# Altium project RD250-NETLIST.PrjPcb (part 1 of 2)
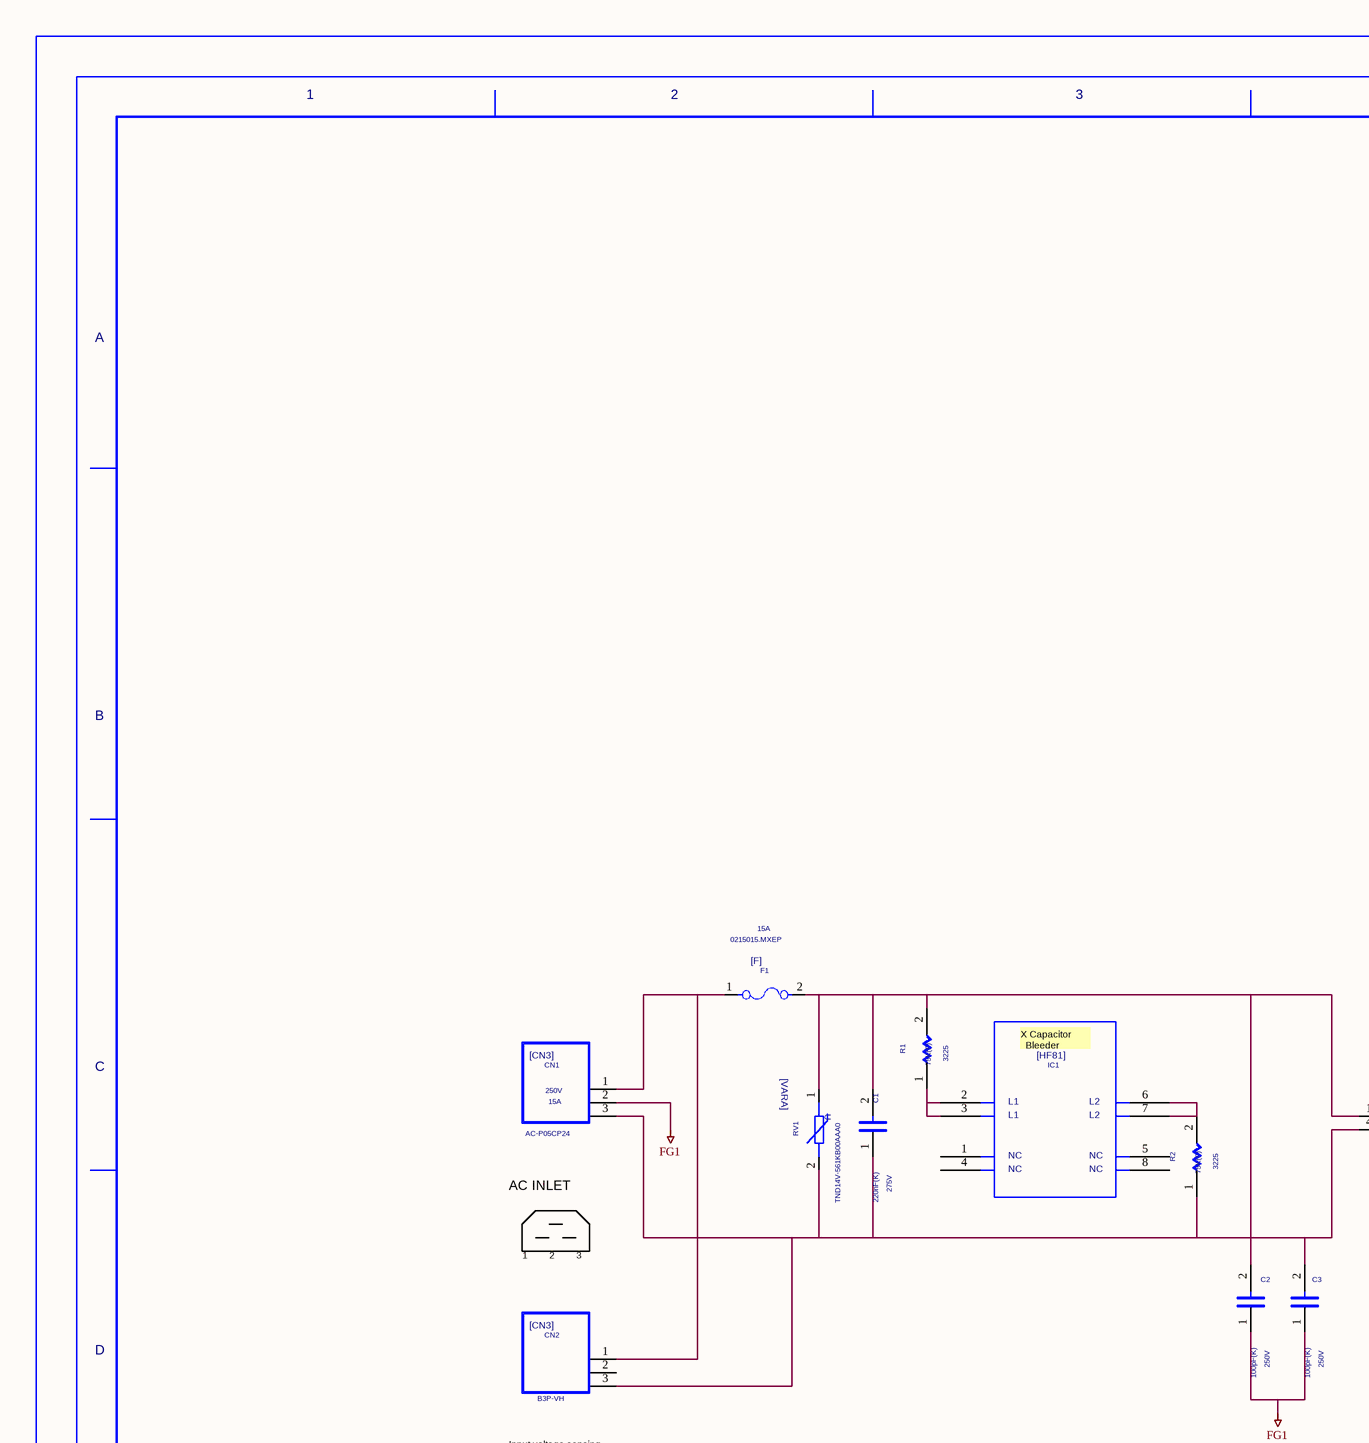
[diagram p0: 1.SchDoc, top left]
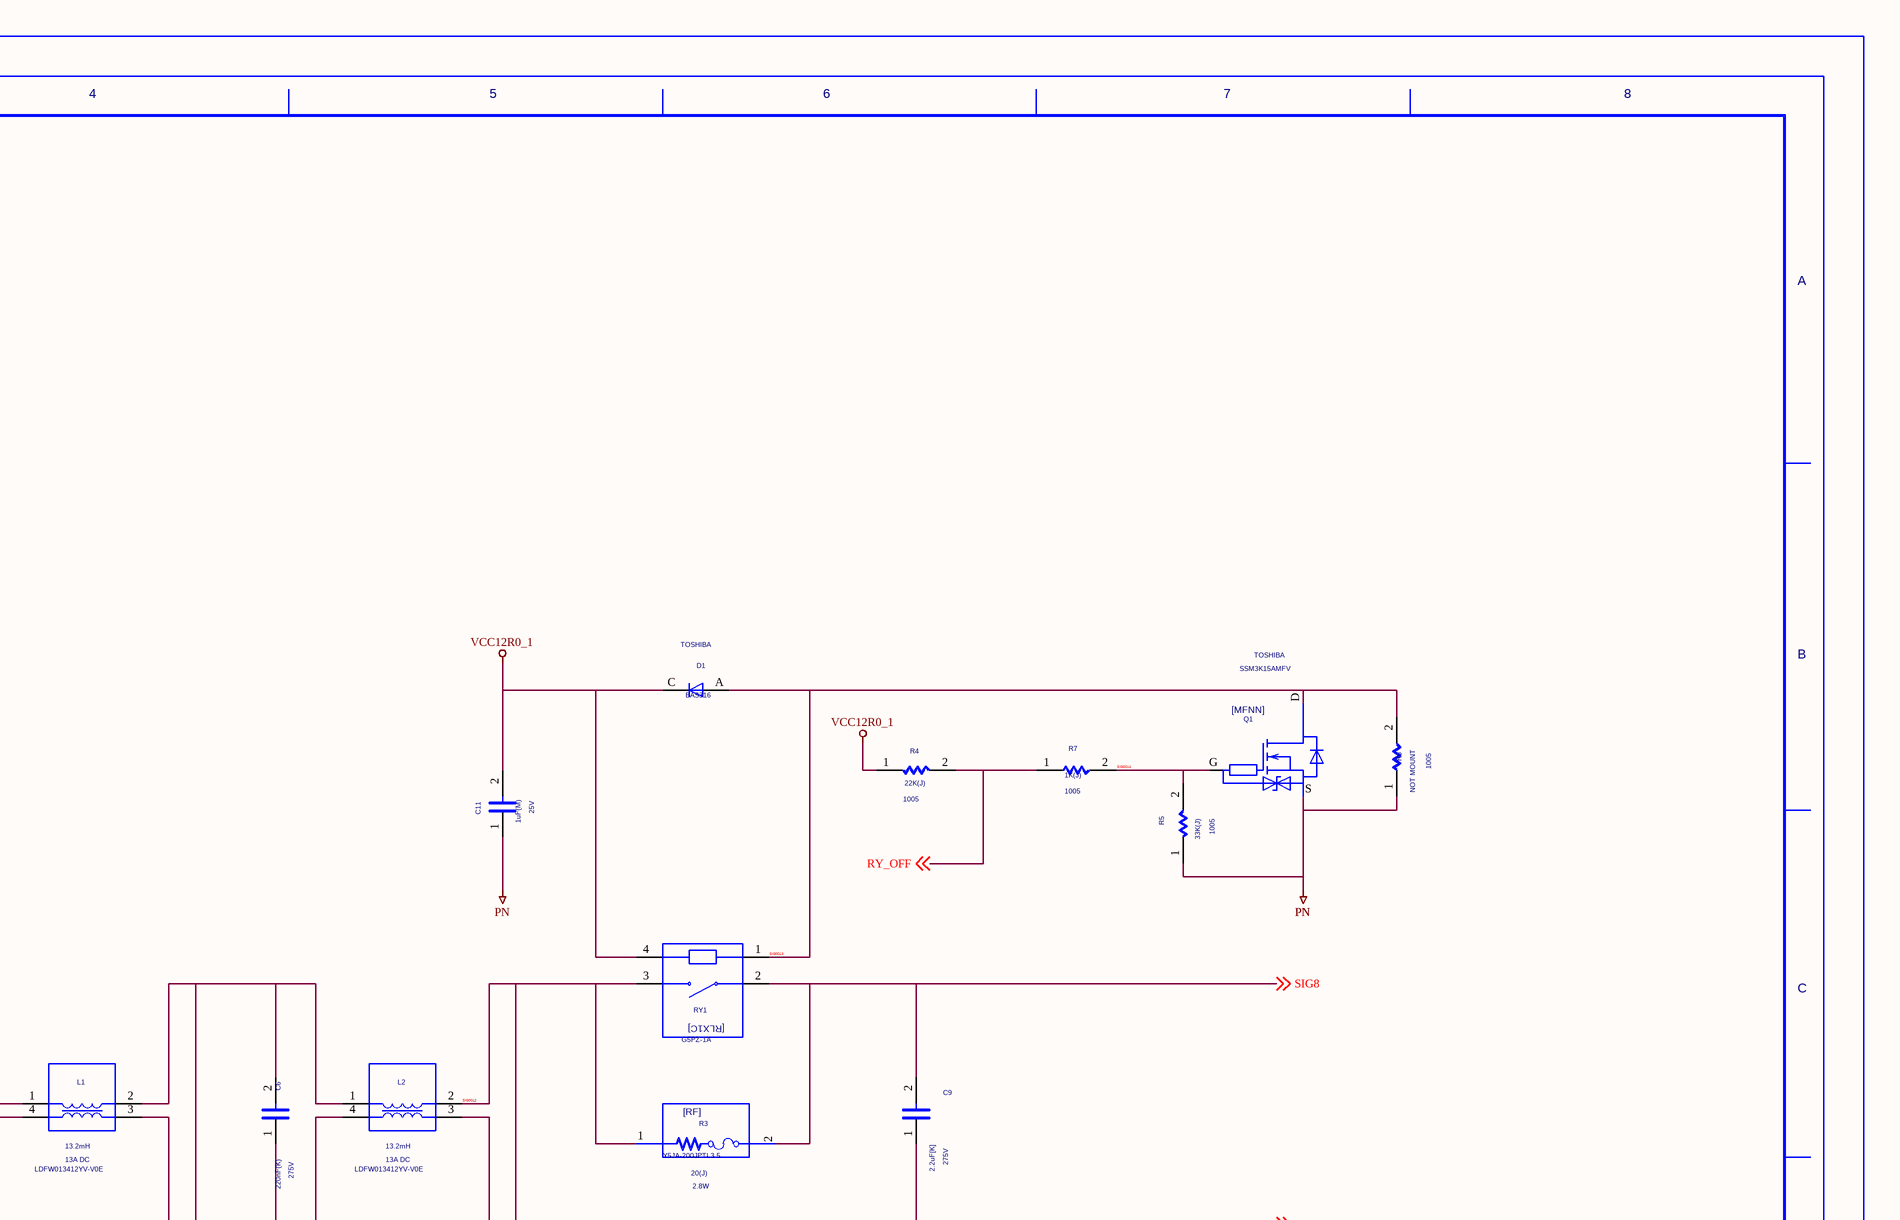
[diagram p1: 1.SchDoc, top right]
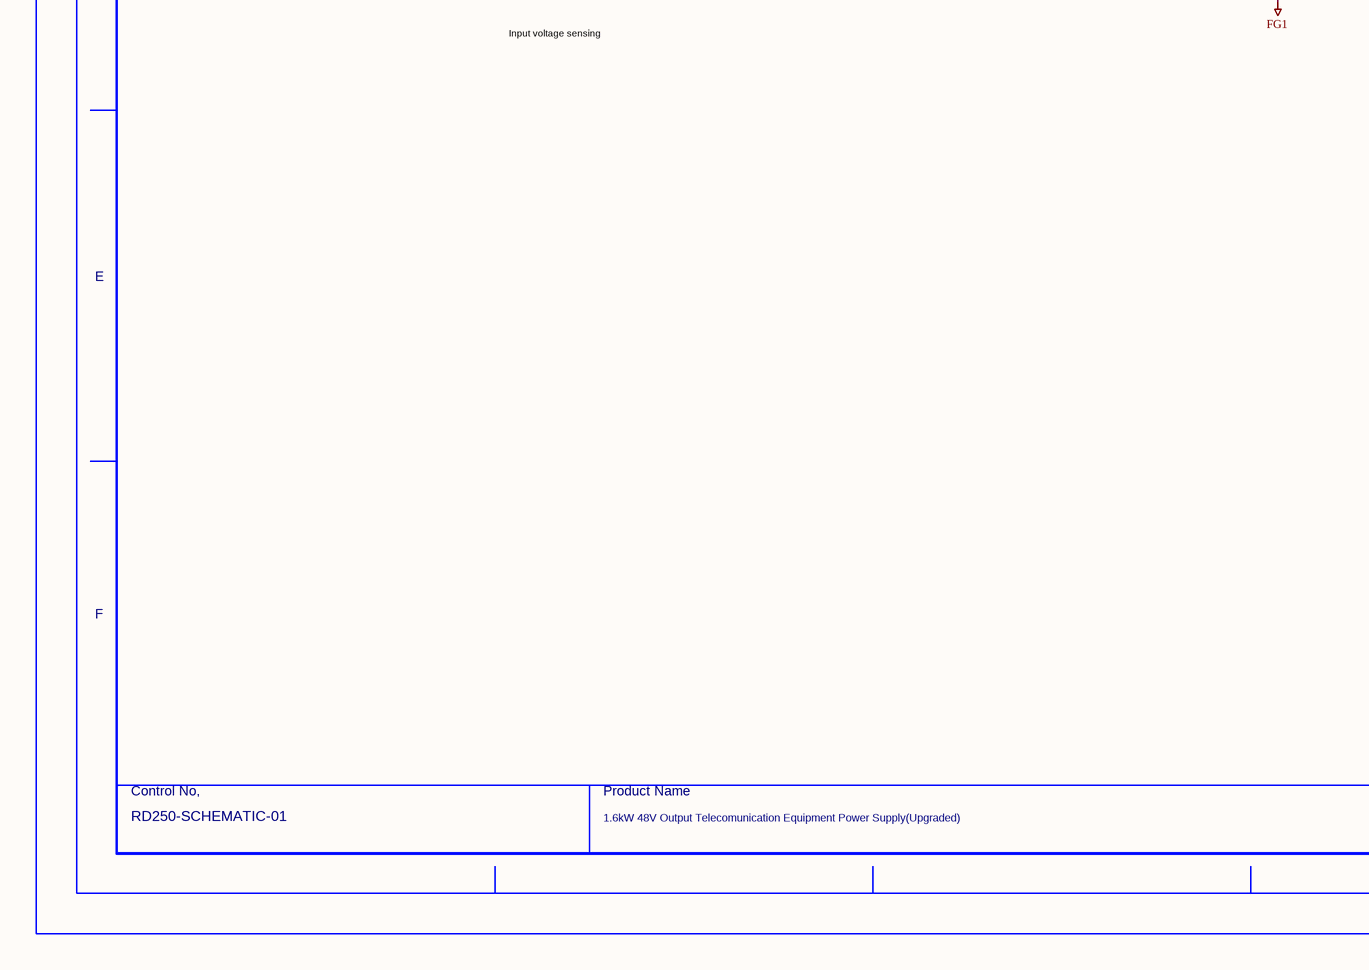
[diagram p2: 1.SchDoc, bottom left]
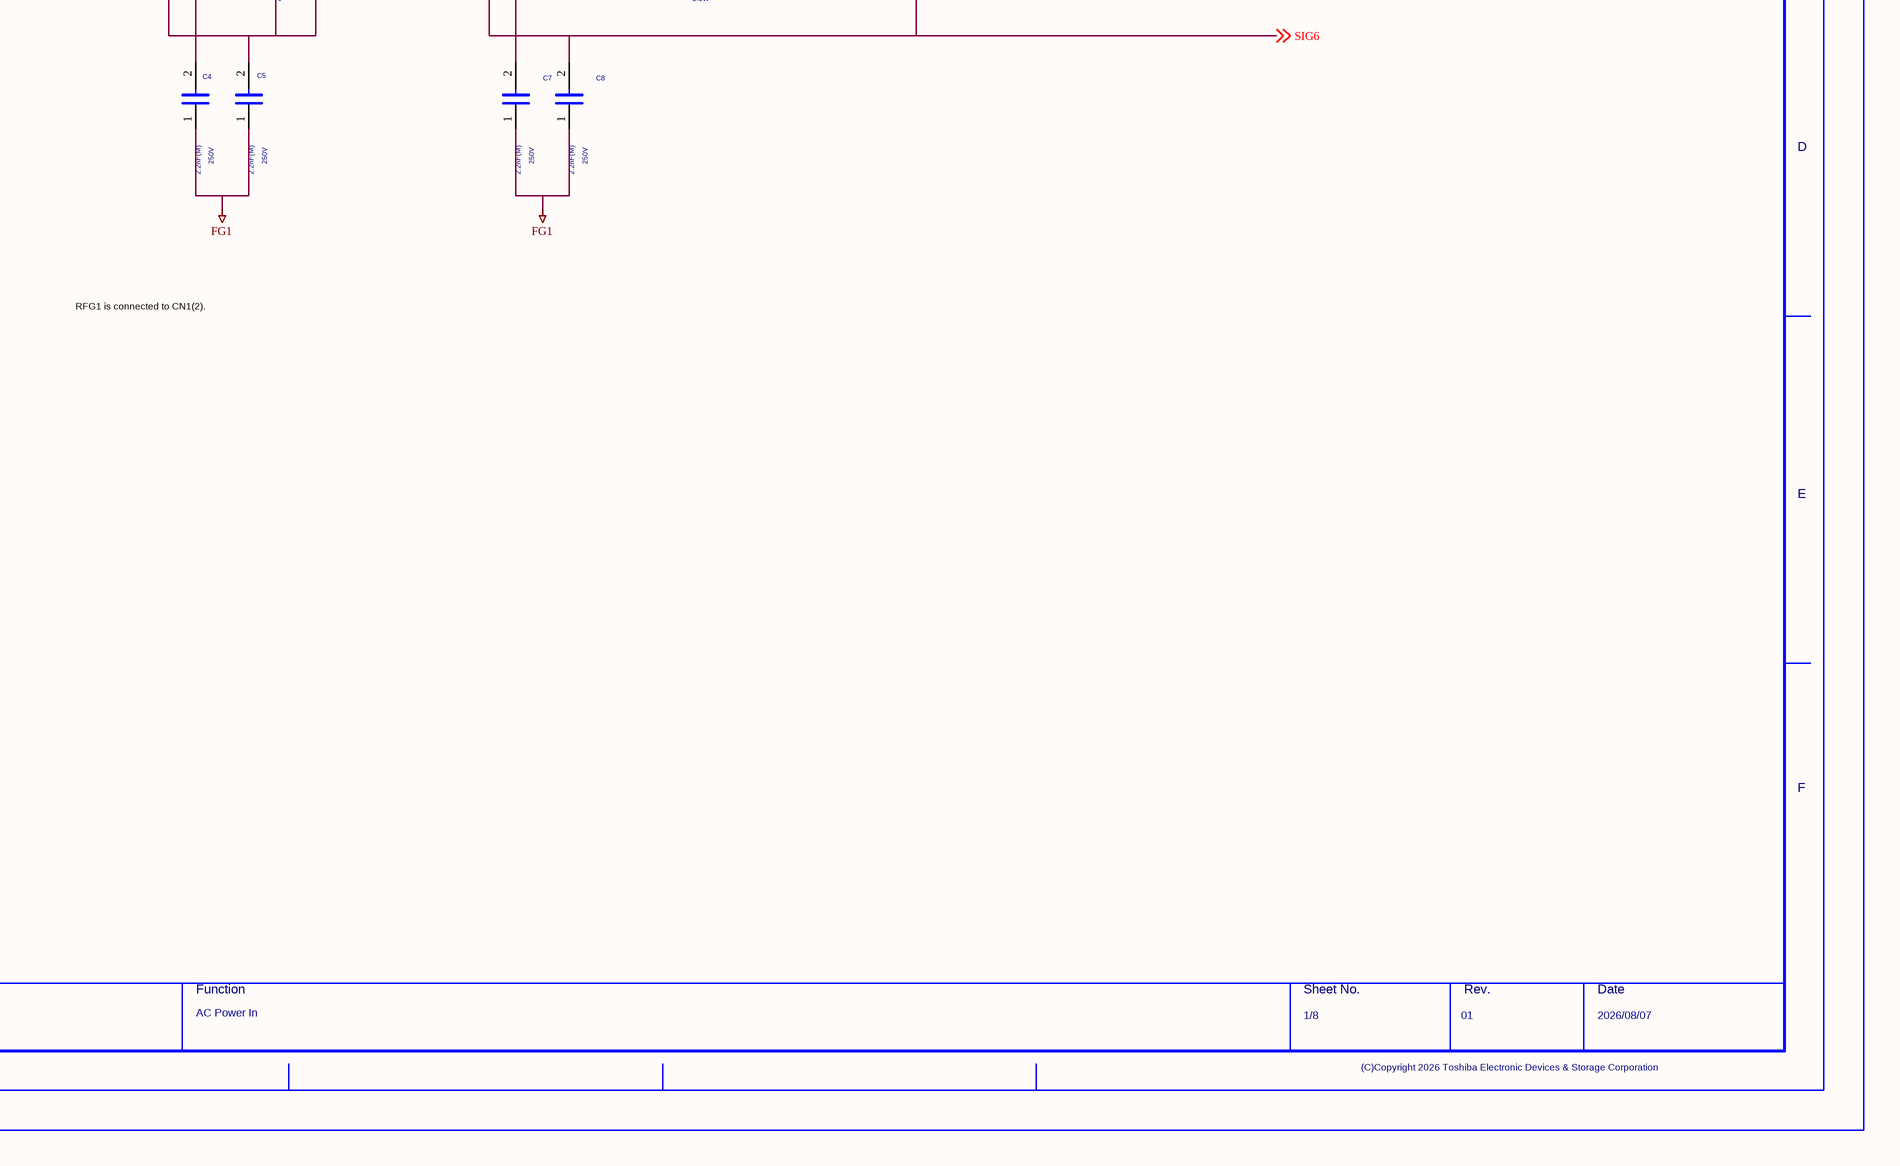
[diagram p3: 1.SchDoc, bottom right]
8 sheets, 547 parts. Net scope: global (net labels, ports and power ports of the same name join across sheets).
Sheets:
  1.SchDoc
  2.SchDoc
  3.SchDoc
  4.SchDoc
  5.SchDoc
  6.SchDoc
  7.SchDoc
  8.SchDoc

## Sheet 1.SchDoc
size 599 x 434 mm

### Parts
(Parts that share a designator on the sheet are numbered #1, #2 ... from top to bottom, then left to right.)
C1  VAL1: 220nF(K)  VAL2: 275V  (hidden comment: C)
C2  VAL1: 100pF(K)  VAL2: 250V  (hidden comment: DE2B3SA101KA3BT02F)
C3  VAL1: 100pF(K)  VAL2: 250V  (hidden comment: DE2B3SA101KA3BT02F)
C4  VAL1: 2.2nF(M)  VAL2: 250V  (hidden comment: DE2E3SA222MN3AT02F)
C5  VAL1: 2.2nF(M)  VAL2: 250V  (hidden comment: DE2E3SA222MN3AT02F)
C6  VAL1: 220nF(K)  VAL2: 275V  (hidden comment: C)
C7  VAL1: 2.2nF(M)  VAL2: 250V  (hidden comment: DE2E3SA222MN3AT02F)
C8  VAL1: 2.2nF(M)  VAL2: 250V  (hidden comment: DE2E3SA222MN3AT02F)
C9  VAL1: 2.2uF[K]  VAL2: 275V  (hidden comment: C)
C11  VAL1: 1uF(M)  VAL2: 25V  (hidden comment: C)
CN1  VAL2: 250V  VAL1: 15A  VAL3: AC-P05CP24  (hidden comment: CN3)
CN2  VAL3: B3P-VH  (hidden comment: CN3)
D1  USERCOMPTEXT3: TOSHIBA  VAL3: BAS316  (hidden comment: D)
F1  VAL1: 15A  VAL3: 0215015.MXEP  (hidden comment: F)
IC1  L81  (value not drawn)
L1  VAL1: 13.2mH  VAL2: 13A DC  (hidden comment: LDFW013412YV-V0E)
L2  VAL1: 13.2mH  VAL2: 13A DC  (hidden comment: LDFW013412YV-V0E)
Q1  USERCOMPTEXT3: TOSHIBA  VAL3: SSM3K15AMFV  (hidden comment: MFNN)
R1  VAL1: 75K(F)  SIZECODESMD: 3225  (hidden comment: R)
R2  VAL1: 75K(F)  SIZECODESMD: 3225  (hidden comment: R)
R3  VAL3: Y5JA-200JPTL3.5  VAL1: 20(J)  VAL2: 2.8W  (hidden comment: Y5JA-330JPTL3_5)
R4  VAL1: 22K(J)  SIZECODESMD: 1005  (hidden comment: R)
R5  VAL1: 33K(J)  SIZECODESMD: 1005  (hidden comment: R)
R6  NOTMOUNT: NOT MOUNT  SIZECODESMD: 1005  (hidden comment: R)
R7  VAL1: 1K(J)  SIZECODESMD: 1005  (hidden comment: R)
RV1  VAL3: TND14V-561KB00AAA0  (hidden comment: VARA)
RY1  G5PZ-1A
U?#1  DATE: 2026/08/07  DRAWINGNUMBER: RD250-SCHEMATIC-01  TITLE: 1.6kW 48V Output Telecomunication / Equipment Power Supply(Upgraded)  FUNCTION: AC Power In  SHEETNUMBER: 1/8  REVISION: 01  (hidden comment: WAKU_A3_TDSC_PSDEV_LOCAL)

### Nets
FG1: C2.1 C3.1 C4.1 C5.1 C7.1 C8.1 CN1.2
PN: C11.1 Q1.S R5.1 R6.1
VCC12R0_1: C11.2 D1.C R4.1 RY1.4
RY_OFF: R4.2 R7.1 ; off-sheet RY_OFF
SIG1: C1.2 C2.2 F1.2 L1.1 R1.2 RV1.1
SIG2: C1.1 C3.2 CN1.3 CN2.3 L1.4 R2.1 RV1.2
SIG6: C8.2 C9.1 L2.3 ; off-sheet SIG6
SIG8: C9.2 R3.2 RY1.2 ; off-sheet SIG8
SIG9: IC1.2 IC1.3 R1.1
SIG10: IC1.6 IC1.7 R2.2
SIG0012: C7.2 L2.2 R3.1 RY1.3
SIG0013: D1.A Q1.D R6.2 RY1.1
SIG0014: Q1.G R5.2 R7.2
SIG193: CN1.1 CN2.1 F1.1
SIG199: C4.2 C6.2 L1.2 L2.1
SIG200: C5.2 C6.1 L1.3 L2.4

Not connected (* = marked no-connect by the designer): CN2 2; IC1 1 4 5 8

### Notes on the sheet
- AC INLET
- 1
- 2
- 3
- Input voltage sensing
- RFG1 is connected to CN1(2).

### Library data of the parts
C1 C6 = C_Dup1: OriginalSymbolOrigin: (2540,7620); VAL3: LE224-M; COMP: PRT_17; MAXGCOUNT: 1; SIZECODESMD: DIP; SAVECOUNT: 0
C2 C3 = DE2B3SA101KA3BT02F: TIME: 18:06:52; UPDATEUSER: t6860224; SAVECOUNT: 1; OriginalSymbolOrigin: (2540,7620); SIZECODESMD: DIP; CHIPSIZE: }}¦}¦¦7.5mmﾘ・
C4 C7 C8 = DE2E3SA222MN3AT02F: TIME: 18:04:40; UPDATEUSER: t6860224; UPDATETIME: 18:05:46; SAVECOUNT: 2; OriginalSymbolOrigin: (2540,7620); CHIPSIZE: }}¦}¦¦7.5mmﾘ・; MAXGCOUNT: 1; SIZECODESMD: DIP
C5 = DE2E3SA222MN3AT02F: SQ_PART_MODEL: CON_2.2N; TIME: 18:04:40; UPDATEUSER: t6860224; UPDATETIME: 18:05:46; SAVECOUNT: 2; OriginalSymbolOrigin: (2540,7620); CHIPSIZE: }}¦}¦¦7.5mmﾘ・; MAXGCOUNT: 1; SIZECODESMD: DIP; ADSCNVFLAG: ON
C9 = C_Dup1: OriginalSymbolOrigin: (2540,7620); VAL3: 890324026034CS; COMP: PRT_18; MAXGCOUNT: 1; SIZECODESMD: DIP; SAVECOUNT: 0
C11 = C_Dup1: OriginalSymbolOrigin: (2540,7620); COMP: PRT_52; CHIPSIZE: 1005; MAXGCOUNT: 1; SAVECOUNT: 0
CN1 = CN3_Dup1: OriginalSymbolOrigin: (2540,17780); COMP: PRT_61; SAVECOUNT: 0
CN2 = CN3: OriginalSymbolOrigin: (2540,17780); USERCOMPTEXT3: }}¦}¦¦; MAXGCOUNT: 1; COMP: G36220401068; ADSCNVFLAG: ON; SAVECOUNT: 0
D1 = D_Dup1: SAVEAREA0: -225,-91,12804,7836; SAVECOUNT: 3; TIME: 14:49:55; UPDATEUSER: 19870035; UPDATETIME: 14:20:16; OriginalSymbolOrigin: (5080,5080); USERCOMPTEXT2: 100V,0.25A; COMP: PRT_26; MAXGCOUNT: 1
F1 = F_Dup1: OriginalSymbolOrigin: (2540,5080); COMP: PRT_21; MAXGCOUNT: 1; SAVECOUNT: 0
IC1 = L81: SAVEAREA0: -12429,-3512,55842,41521; TIME: 18:31:00; UPDATEUSER: cae; UPDATETIME: 11:10:50; SAVECOUNT: 13; OriginalSymbolOrigin: (7620,35560); VAL3: HF81; COMP: PRT_45
L1 L2 = LDFW013412YV-V0E: SAVEAREA0: -19486,-4937,42112,22919; TIME: 15:15:31; UPDATEUSER: t4887876; UPDATETIME: 16:45:41; SAVECOUNT: 10; OriginalSymbolOrigin: (5080,15240); USERCOMPTEXT1: #%ﾘ%; DEVICENAME: DLW21HN670SQ2
Q1 = MFNN: SAVECOUNT: 25; SAVEAREA0: -2884,-274,25430,18334; TIME: 08:01:03; UPDATEUSER: sato-yr; UPDATETIME: 13:42:20; OriginalSymbolOrigin: (2540,17780); MAXGCOUNT: 1; COMP: GDM410000663; ADSCNVFLAG: ON; ADSCOMPONENTNAME: Q_MFNN
R1 R2 = R_Dup1: VAL2: 500mW; OriginalSymbolOrigin: (5080,5080); COMP: PRT_23; MAXGCOUNT: 1; SAVECOUNT: 0
R3 = Y5JA-330JPTL3_5: TIME: 16:26:39; UPDATEUSER: t4887876; UPDATETIME: 20:40:35; SAVECOUNT: 5; OriginalSymbolOrigin: (-1270,12700); MAXGCOUNT: 1; CHIPSIZE: 13x9xH25.5
R4 R5 R7 = R_Dup1: VAL2: 63mW; OriginalSymbolOrigin: (5080,5080); COMP: GDM010004481; CHIPSIZE: 1608; MAXGCOUNT: 1; SAVECOUNT: 0
R6 = R_Dup1: OriginalSymbolOrigin: (5080,5080); COMP: GDM010004481; CHIPSIZE: 1608; MAXGCOUNT: 1; SAVECOUNT: 0
RV1 = VARA: SAVEAREA0: -9950,-8554,25168,13619; SAVECOUNT: 12; TIME: 09:56:50; UPDATEUSER: tomizawa-y; OriginalSymbolOrigin: (2540,5080); COMP: PRT_37; VAL1: 560V; MAXGCOUNT: 1
RY1 = G5PZ-1A: SAVECOUNT: 11; SAVEAREA0: -9347,-440,34039,23986; TIME: 18:43:12; UPDATEUSER: t6860224; UPDATETIME: 18:43:42; OriginalSymbolOrigin: (5080,20320); MAXGCOUNT: 1
U?#1 = WAKU_A3_TDSC_PSDEV_LOCAL: PLOTTIME: HH:MM; SAVEAREA0: -311037,-554865,914355,115662; TIME: 10:19:22; UPDATEUSER: t5459927; UPDATETIME: 17:59:49; SAVECOUNT: 3; ZONEOFFSETX: 36; ZONEOFFSETY: -24; OriginalSymbolOrigin: (0,434340); SHTSAVECOUNT: 92; PAGENUMBER: 1; DESIGNED: TOSHIBA

## Sheet 2.SchDoc
size 599 x 434 mm
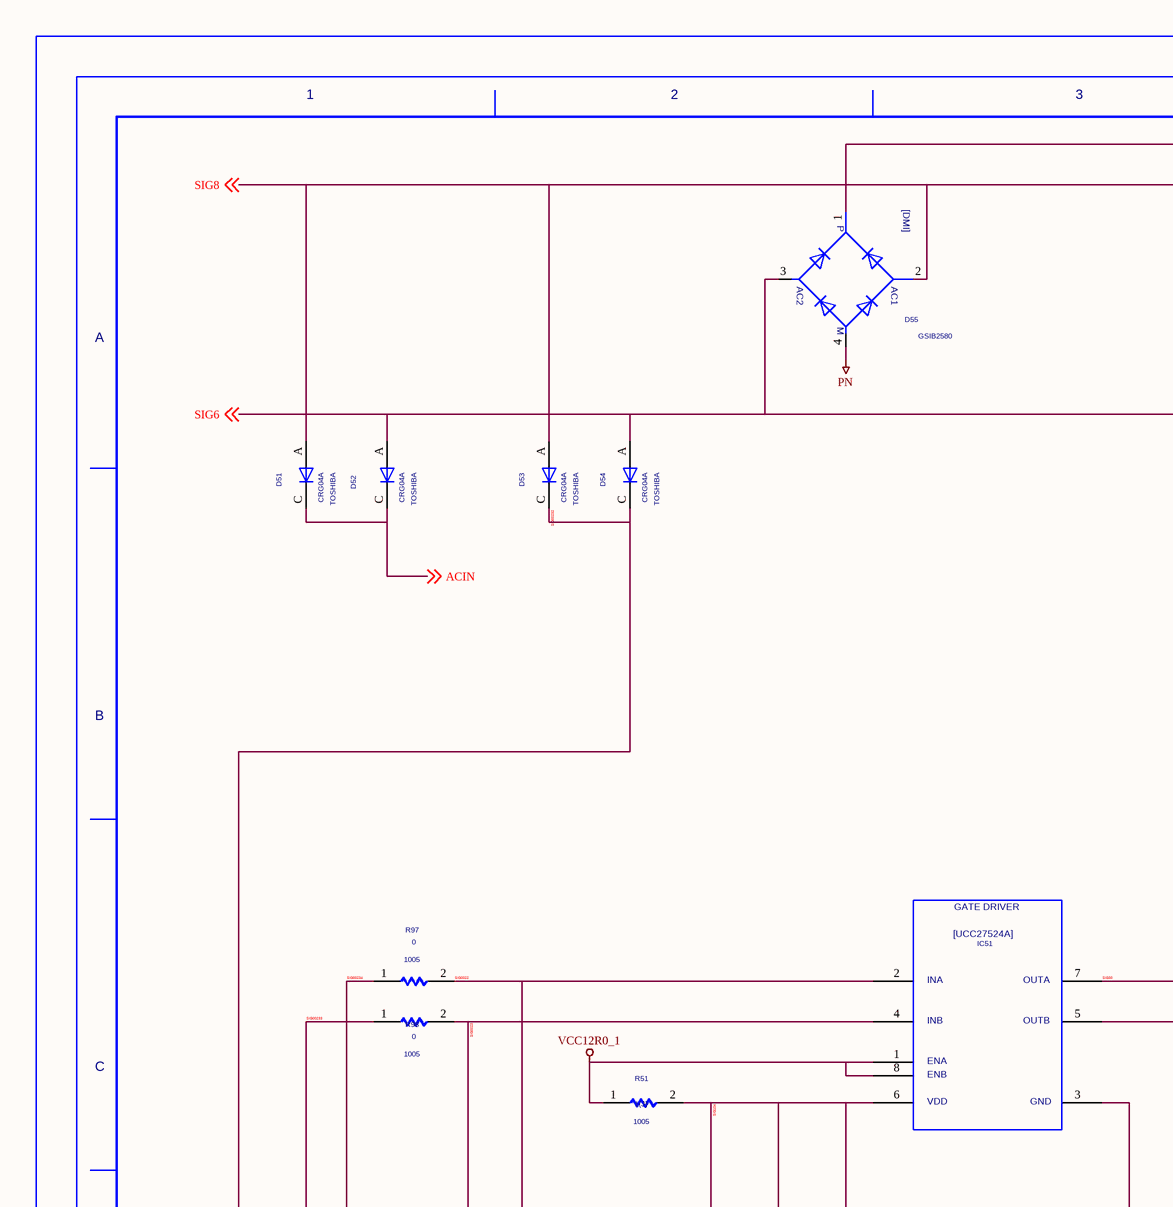
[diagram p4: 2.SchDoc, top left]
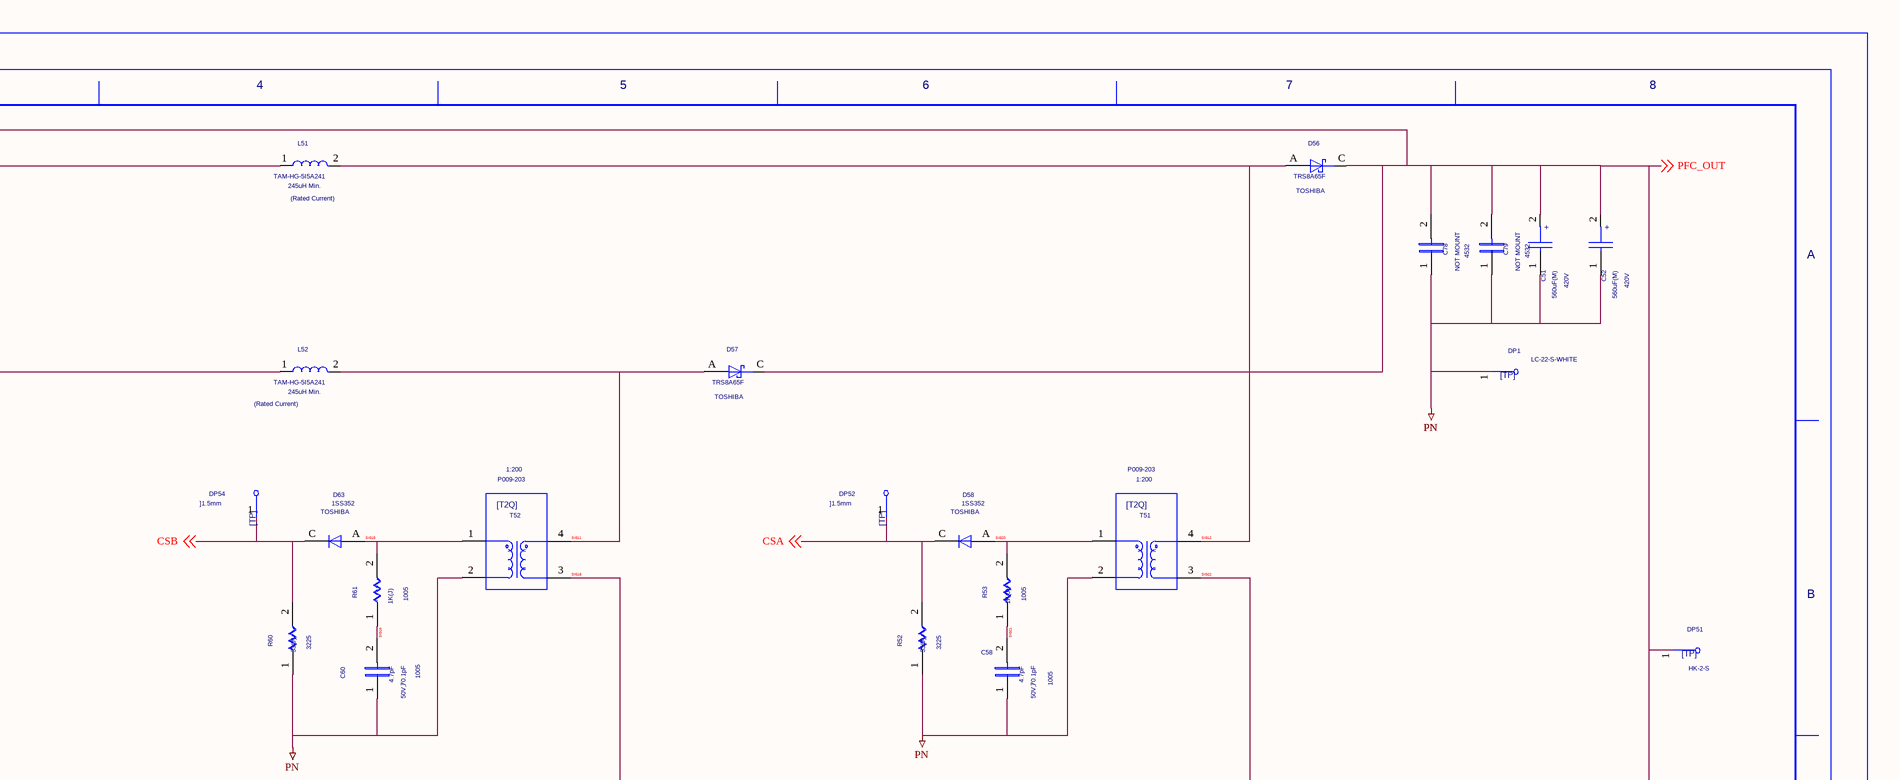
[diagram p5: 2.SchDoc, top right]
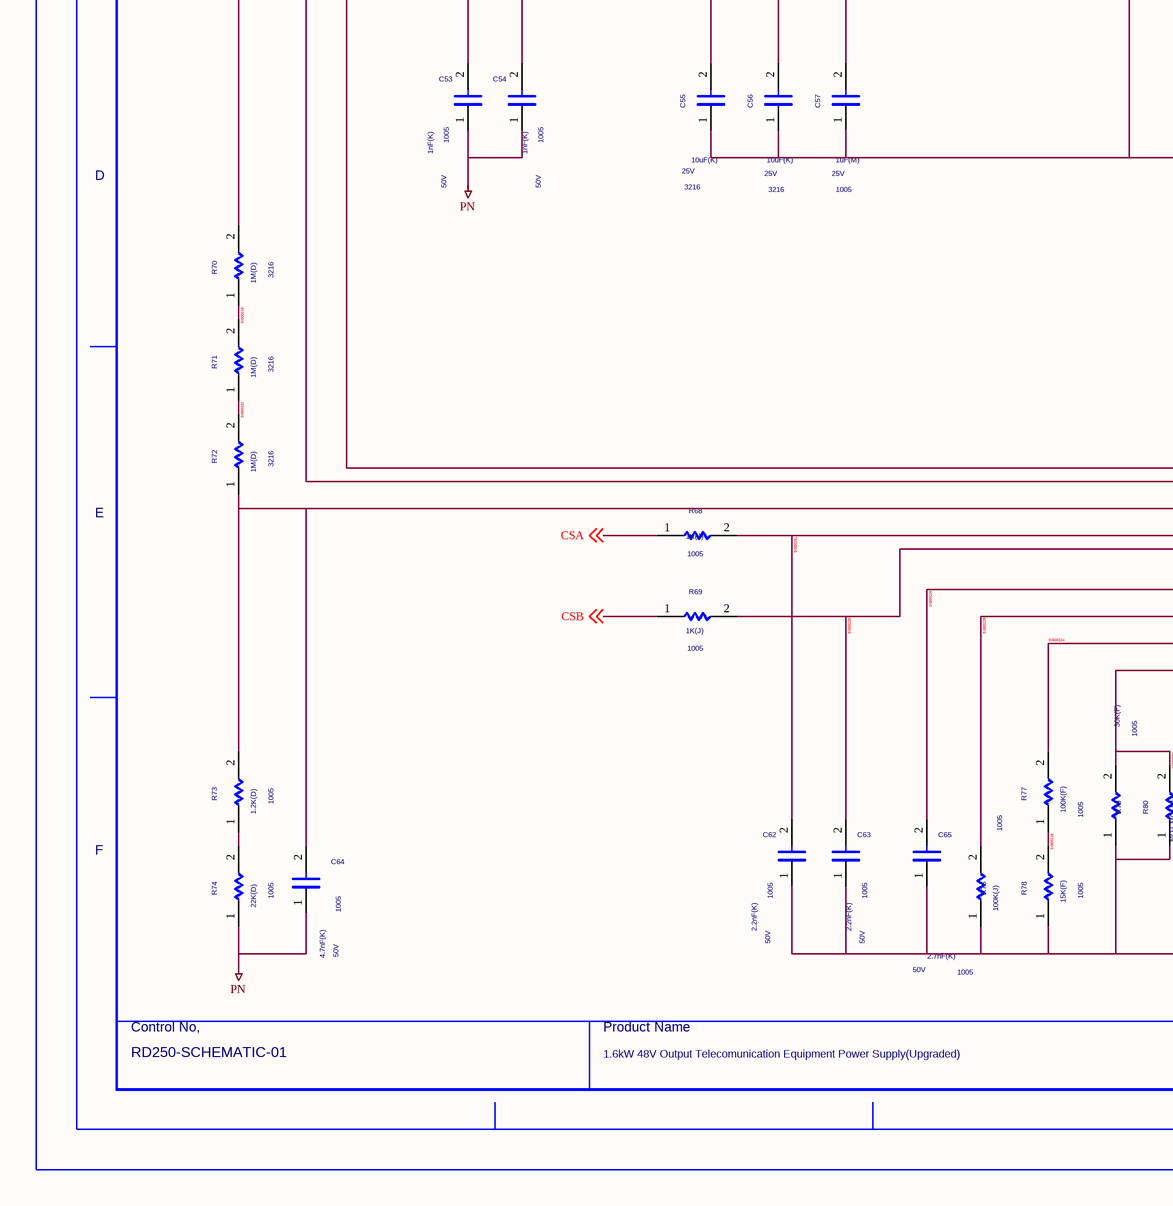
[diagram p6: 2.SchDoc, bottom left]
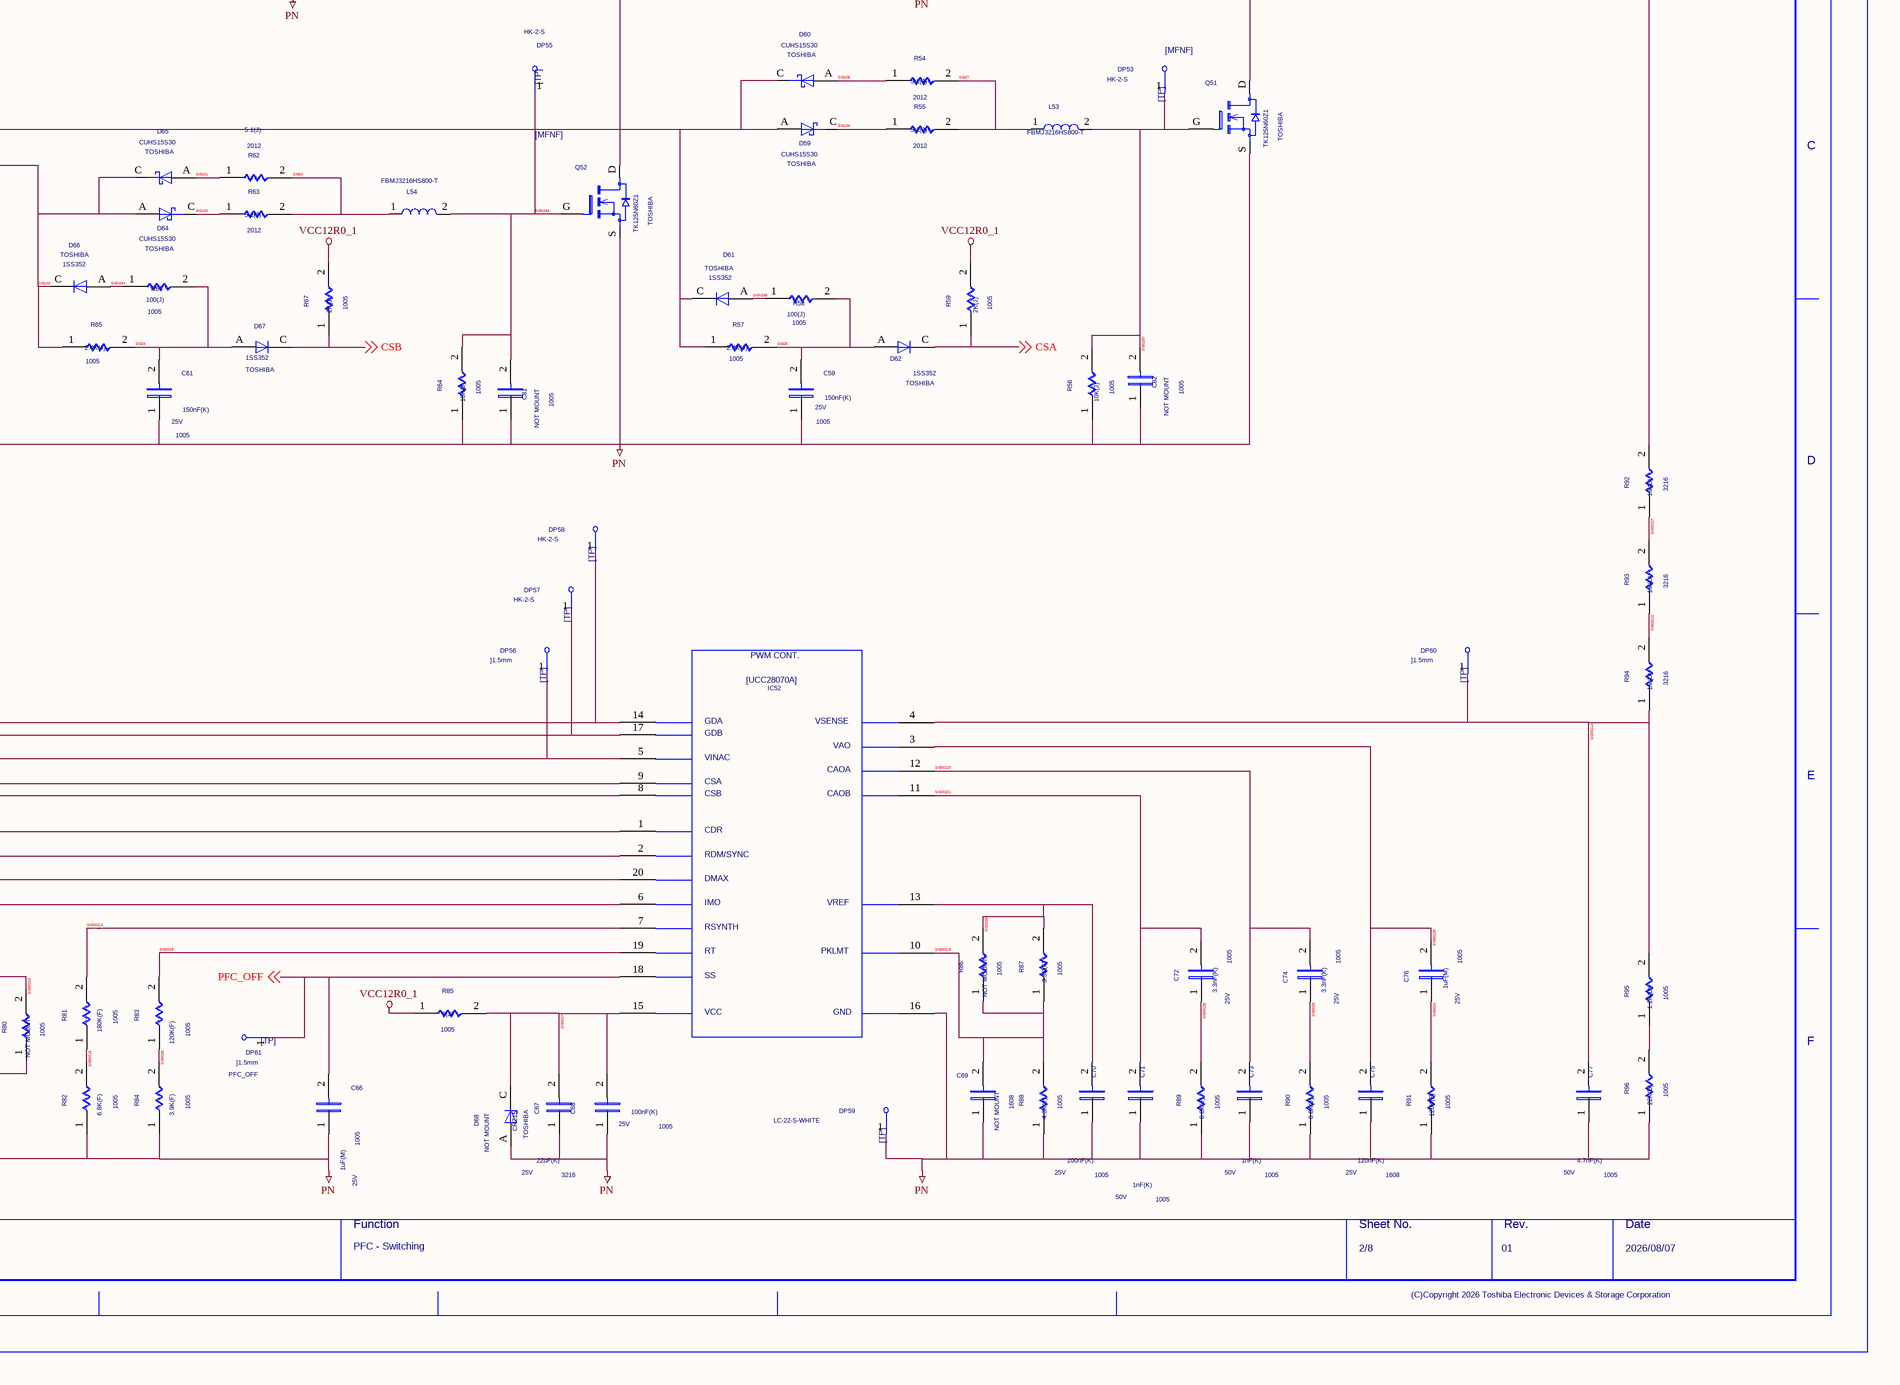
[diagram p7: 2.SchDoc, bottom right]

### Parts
(Parts that share a designator on the sheet are numbered #1, #2 ... from top to bottom, then left to right.)
C51  VAL1: 560uF(M)  VAL2: 420V  (hidden comment: EKHE421VSN561MR35Z)
C52  VAL1: 560uF(M)  VAL2: 420V  (hidden comment: EKHE421VSN561MR35Z)
C53  VAL1: 1nF(K)  VAL2: 50V  SIZECODESMD: 1005  (hidden comment: C)
C54  VAL1: 1nF(K)  VAL2: 50V  SIZECODESMD: 1005  (hidden comment: C)
C55  VAL1: 10uF(K)  VAL2: 25V  SIZECODESMD: 3216  (hidden comment: C)
C56  VAL1: 10uF(K)  VAL2: 25V  SIZECODESMD: 3216  (hidden comment: C)
C57  VAL1: 1uF(M)  VAL2: 25V  SIZECODESMD: 1005  (hidden comment: C)
C58  VAL1: 4.7pF  VAL2: 50V,ｱ0.1pF  SIZECODESMD: 1005  (hidden comment: C)
C59  VAL1: 150nF(K)  VAL2: 25V  SIZECODESMD: 1005  (hidden comment: C)
C60  VAL1: 4.7pF  VAL2: 50V,ｱ0.1pF  SIZECODESMD: 1005  (hidden comment: C)
C61  VAL1: 150nF(K)  VAL2: 25V  SIZECODESMD: 1005  (hidden comment: C)
C62  VAL1: 2.2nF(K)  VAL2: 50V  SIZECODESMD: 1005  (hidden comment: C)
C63  VAL1: 2.2nF(K)  VAL2: 50V  SIZECODESMD: 1005  (hidden comment: C)
C64  VAL1: 4.7nF(K)  VAL2: 50V  SIZECODESMD: 1005  (hidden comment: C)
C65  VAL1: 2.7nF(K)  VAL2: 50V  SIZECODESMD: 1005  (hidden comment: C)
C66  VAL1: 1uF(M)  VAL2: 25V  SIZECODESMD: 1005  (hidden comment: C)
C67  VAL1: 22uF(K)  VAL2: 25V  SIZECODESMD: 3216  (hidden comment: C)
C68  VAL1: 100nF(K)  VAL2: 25V  SIZECODESMD: 1005  (hidden comment: C)
C69  NOTMOUNT: NOT MOUNT  SIZECODESMD: 1608  (hidden comment: C)
C70  VAL1: 100nF(K)  VAL2: 25V  SIZECODESMD: 1005  (hidden comment: C)
C71  VAL1: 1nF(K)  VAL2: 50V  SIZECODESMD: 1005  (hidden comment: C)
C72  VAL1: 3.3nF(K)  VAL2: 25V  SIZECODESMD: 1005  (hidden comment: C)
C73  VAL1: 1nF(K)  VAL2: 50V  SIZECODESMD: 1005  (hidden comment: C)
C74  VAL1: 3.3nF(K)  VAL2: 25V  SIZECODESMD: 1005  (hidden comment: C)
C75  VAL1: 120nF(K)  VAL2: 25V  SIZECODESMD: 1608  (hidden comment: C)
C76  VAL1: 1uF(M)  VAL2: 25V  SIZECODESMD: 1005  (hidden comment: C)
C77  VAL1: 4.7nF(K)  VAL2: 50V  SIZECODESMD: 1005  (hidden comment: C)
C78  NOTMOUNT: NOT MOUNT  SIZECODESMD: 4532  (hidden comment: C4532)
C79  NOTMOUNT: NOT MOUNT  SIZECODESMD: 4532  (hidden comment: C4532)
C81  NOTMOUNT: NOT MOUNT  SIZECODESMD: 1005  (hidden comment: C)
C82  NOTMOUNT: NOT MOUNT  SIZECODESMD: 1005  (hidden comment: C)
D51  USERCOMPTEXT3: TOSHIBA  (hidden comment: CRG04A)
D52  USERCOMPTEXT3: TOSHIBA  (hidden comment: CRG04A)
D53  USERCOMPTEXT3: TOSHIBA  (hidden comment: CRG04A)
D54  USERCOMPTEXT3: TOSHIBA  (hidden comment: CRG04A)
D55  GSIB2580
D56  VAL3: TRS8A65F  USERCOMPTEXT3: TOSHIBA  (hidden comment: SBD_TO-220-2L)
D57  VAL3: TRS8A65F  USERCOMPTEXT3: TOSHIBA  (hidden comment: SBD_TO-220-2L)
D58  USERCOMPTEXT3: TOSHIBA  VAL3: 1SS352  (hidden comment: D)
D59  USERCOMPTEXT3: TOSHIBA  (hidden comment: CUHS15S30)
D60  USERCOMPTEXT3: TOSHIBA  (hidden comment: CUHS15S30)
D61  USERCOMPTEXT3: TOSHIBA  VAL3: 1SS352  (hidden comment: D)
D62  USERCOMPTEXT3: TOSHIBA  VAL3: 1SS352  (hidden comment: D)
D63  USERCOMPTEXT3: TOSHIBA  VAL3: 1SS352  (hidden comment: D)
D64  USERCOMPTEXT3: TOSHIBA  (hidden comment: CUHS15S30)
D65  USERCOMPTEXT3: TOSHIBA  (hidden comment: CUHS15S30)
D66  USERCOMPTEXT3: TOSHIBA  VAL3: 1SS352  (hidden comment: D)
D67  USERCOMPTEXT3: TOSHIBA  VAL3: 1SS352  (hidden comment: D)
D68  NOTMOUNT: NOT MOUNT  USERCOMPTEXT3: TOSHIBA  VAL3: CRZ15  (hidden comment: ZD)
DP1  VAL3: LC-22-S-WHITE  (hidden comment: TP)
DP51  VAL3: HK-2-S  (hidden comment: TP)
DP52  USERCOMPTEXT1: ]1.5mm  (hidden comment: TP)
DP53  VAL3: HK-2-S  (hidden comment: TP)
DP54  USERCOMPTEXT1: ]1.5mm  (hidden comment: TP)
DP55  VAL3: HK-2-S  (hidden comment: TP)
DP56  USERCOMPTEXT1: ]1.5mm  (hidden comment: TP)
DP57  VAL3: HK-2-S  (hidden comment: TP)
DP58  VAL3: HK-2-S  (hidden comment: TP)
DP59  VAL3: LC-22-S-WHITE  (hidden comment: TP)
DP60  USERCOMPTEXT1: ]1.5mm  (hidden comment: TP)
DP61  COMPCOMMENT: PFC_OFF  USERCOMPTEXT1: ]1.5mm  (hidden comment: TP)
IC51  L27524  (value not drawn)
IC52  L28070  (value not drawn)
L51  VAL1: 245uH Min.  VAL2: (Rated Current)  VAL3: TAM-HG-5I5A241  (hidden comment: L)
L52  VAL1: 245uH Min.  VAL2: (Rated Current)  VAL3: TAM-HG-5I5A241  (hidden comment: L)
L53  VAL3: FBMJ3216HS800-T  (hidden comment: L)
L54  VAL3: FBMJ3216HS800-T  (hidden comment: L)
Q51  USERCOMPTEXT3: TOSHIBA  (hidden comment: TK125N60Z1)
Q52  USERCOMPTEXT3: TOSHIBA  (hidden comment: TK125N60Z1)
R51  VAL1: 1(J)  SIZECODESMD: 1005  (hidden comment: R)
R52  VAL1: 33(J)  SIZECODESMD: 3225  (hidden comment: R)
R53  VAL1: 1K(J)  SIZECODESMD: 1005  (hidden comment: R)
R54  VAL1: 5.1(J)  SIZECODESMD: 2012  (hidden comment: R)
R55  VAL1: 5.1(J)  SIZECODESMD: 2012  (hidden comment: R)
R56  VAL1: 10K(J)  SIZECODESMD: 1005  (hidden comment: R)
R57  VAL1: 2.4K(J)  SIZECODESMD: 1005  (hidden comment: R)
R58  VAL1: 100(J)  SIZECODESMD: 1005  (hidden comment: R)
R59  VAL1: 2K(J)  SIZECODESMD: 1005  (hidden comment: R)
R60  VAL1: 33(J)  SIZECODESMD: 3225  (hidden comment: R)
R61  VAL1: 1K(J)  SIZECODESMD: 1005  (hidden comment: R)
R62  VAL1: 5.1(J)  SIZECODESMD: 2012  (hidden comment: R)
R63  VAL1: 5.1(J)  SIZECODESMD: 2012  (hidden comment: R)
R64  VAL1: 10K(J)  SIZECODESMD: 1005  (hidden comment: R)
R65  VAL1: 2.4K(J)  SIZECODESMD: 1005  (hidden comment: R)
R66  VAL1: 100(J)  SIZECODESMD: 1005  (hidden comment: R)
R67  VAL1: 2K(J)  SIZECODESMD: 1005  (hidden comment: R)
R68  VAL1: 1K(J)  SIZECODESMD: 1005  (hidden comment: R)
R69  VAL1: 1K(J)  SIZECODESMD: 1005  (hidden comment: R)
R70  VAL1: 1M(D)  SIZECODESMD: 3216  (hidden comment: R)
R71  VAL1: 1M(D)  SIZECODESMD: 3216  (hidden comment: R)
R72  VAL1: 1M(D)  SIZECODESMD: 3216  (hidden comment: R)
R73  VAL1: 1.2K(D)  SIZECODESMD: 1005  (hidden comment: R)
R74  VAL1: 22K(D)  SIZECODESMD: 1005  (hidden comment: R)
R76  VAL1: 100K(J)  SIZECODESMD: 1005  (hidden comment: R)
R77  VAL1: 100K(F)  SIZECODESMD: 1005  (hidden comment: R)
R78  VAL1: 15K(F)  SIZECODESMD: 1005  (hidden comment: R)
R79  VAL1: 30K(F)  SIZECODESMD: 1005  (hidden comment: R)
R80  NOTMOUNT: NOT MOUNT  SIZECODESMD: 1005  (hidden comment: R)
R81  VAL1: 180K(F)  SIZECODESMD: 1005  (hidden comment: R)
R82  VAL1: 6.8K(F)  SIZECODESMD: 1005  (hidden comment: R)
R83  VAL1: 120K(F)  SIZECODESMD: 1005  (hidden comment: R)
R84  VAL1: 3.9K(F)  SIZECODESMD: 1005  (hidden comment: R)
R85  VAL1: 1(J)  SIZECODESMD: 1005  (hidden comment: R)
R86  NOTMOUNT: NOT MOUNT  SIZECODESMD: 1005  (hidden comment: R)
R87  VAL1: 3.3K(F)  SIZECODESMD: 1005  (hidden comment: R)
R88  VAL1: 4.3K(J)  SIZECODESMD: 1005  (hidden comment: R)
R89  VAL1: 6.8K(J)  SIZECODESMD: 1005  (hidden comment: R)
R90  VAL1: 6.8K(J)  SIZECODESMD: 1005  (hidden comment: R)
R91  VAL1: 120K(F)  SIZECODESMD: 1005  (hidden comment: R)
R92  VAL1: 1M(D)  SIZECODESMD: 3216  (hidden comment: R)
R93  VAL1: 1M(D)  SIZECODESMD: 3216  (hidden comment: R)
R94  VAL1: 1M(D)  SIZECODESMD: 3216  (hidden comment: R)
R95  VAL1: 1.2K(D)  SIZECODESMD: 1005  (hidden comment: R)
R96  VAL1: 22K(D)  SIZECODESMD: 1005  (hidden comment: R)
R97  VAL1: 0  SIZECODESMD: 1005  (hidden comment: R)
R98  VAL1: 0  SIZECODESMD: 1005  (hidden comment: R)
T51  VAL1: 1:200  VAL3: P009-203  (hidden comment: T2Q)
T52  VAL1: 1:200  VAL3: P009-203  (hidden comment: T2Q)
U?#2  DATE: 2026/08/07  DRAWINGNUMBER: RD250-SCHEMATIC-01  TITLE: 1.6kW 48V Output Telecomunication / Equipment Power Supply(Upgraded)  FUNCTION: PFC - Switching  SHEETNUMBER: 2/8  REVISION: 01  (hidden comment: WAKU_A3_TDSC_PSDEV_LOCAL)

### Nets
PN: C51.1 C52.1 C53.1 C54.1 C55.1 C56.1 C57.1 C58.1 C59.1 C60.1 C61.1 C62.1 C63.1 C64.1 C65.1 C66.1 C67.1 C68.1 C69.1 C70.1 C71.1 C73.1 C75.1 C77.1 C78.1 C79.1 C81.1 C82.1 D55.4 D68.A DP1.1 DP59.1 IC51.3 IC52.16 Q51.S Q52.S R52.1 R56.1 R60.1 R64.1 R74.1 R76.1 R78.1 R79.1 R80.1 R82.1 R84.1 R88.1 R89.1 R90.1 R91.1 R96.1 T51.2 T52.2
VCC12R0_1: IC51.1 IC51.8 R51.1 R59.2 R67.2 R85.1
ACIN: D51.C D52.C ; off-sheet ACIN
CSA: D58.C D62.C DP52.1 R52.2 R59.1 R68.1 ; off-sheet CSA
CSB: D63.C D67.C DP54.1 R60.2 R67.1 R69.1 ; off-sheet CSB
PFC_OFF: C66.2 DP61.1 IC52.18 ; off-sheet PFC_OFF
PFC_OUT: C51.2 C52.2 C78.2 C79.2 D55.1 D56.C D57.C DP51.1 R92.2 ; off-sheet PFC_OUT
SIG6: D52.A D54.A D55.3 L52.1 ; off-sheet SIG6
SIG8: D51.A D53.A D55.2 L51.1 ; off-sheet SIG8
SIG11: D57.A L52.2 T52.4
SIG12: D56.A L51.2 T51.4
SIG15: D63.A R61.2 T52.1
SIG16: C60.2 R61.1
SIG18: Q52.D T52.3
SIG20: D58.A R53.2 T51.1
SIG21: C58.2 R53.1
SIG22: Q51.D T51.3
SIG0022: C54.2 IC51.2 R97.2
SIG23: L54.1 R62.2 R63.2
SIG0023: C53.2 IC51.4 R98.2
SIG24: C61.2 D67.A R65.2 R66.2
SIG0024: C76.1 R91.2
SIG25: C59.2 D62.A R57.2 R58.2
SIG0025: C74.1 R90.2
SIG0026: C70.2 IC52.13 R86.2 R87.2
SIG27: L53.1 R54.2 R55.2
SIG0027: C67.2 C68.2 D68.C IC52.15 R85.2
SIG0028: R83.1 R84.2
SIG0029: IC52.19 R83.2
SIG30: D59.A D60.C D61.C IC51.7 R57.1
SIG100: D64.C R63.1
SIG101: D65.A R62.1
SIG102: D64.A D65.C D66.C IC51.5 R65.1
SIG104: C55.2 C56.2 C57.2 IC51.6 R51.2
SIG105: D60.A R54.1
SIG106: D59.C R55.1
SIG00210: R93.1 R94.2
SIG00211: C64.2 DP56.1 IC52.5 R72.1 R73.2
SIG00212: R95.1 R96.2
SIG00213: IC52.7 R81.2
SIG00214: C77.2 DP60.1 IC52.4 R94.1 R95.2
SIG00215: R81.1 R82.2
SIG00216: R77.1 R78.2
SIG00217: R73.1 R74.2
SIG00218: R70.1 R71.2
SIG00219: C69.2 IC52.10 R86.1 R87.1 R88.2
SIG00220: C73.2 C74.2 IC52.12
SIG00221: C71.2 C72.2 IC52.11
SIG00222: R71.1 R72.2
SIG00223: IC52.6 R79.2 R80.2
SIG00224: IC52.20 R77.2
SIG00225: C63.2 IC52.8 R69.2
SIG00226: C65.2 IC52.1
SIG00227: R92.1 R93.2
SIG00228: IC52.2 R76.2
SIG00229: C75.2 C76.2 IC52.3
SIG00230: C72.1 R89.2
SIG00231: C62.2 IC52.9 R68.2
SIG00232: D53.C D54.C R70.2
SIG00233: DP57.1 IC52.17 R98.1
SIG00234: DP58.1 IC52.14 R97.1
SIGN254: D66.A R66.1
SIGN255: D61.A R58.1
SIGN266: C81.2 DP55.1 L54.2 Q52.G R64.2
SIGN267: C82.2 DP53.1 L53.2 Q51.G R56.2

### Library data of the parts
C51 C52 = EKHE421VSN561MR35Z: SQ_PART_MODEL: CON_560U; SAVEAREA0: -1450,-153,20294,13055; SAVECOUNT: 55; TIME: 15:02:55; UPDATEUSER: t4887876; UPDATETIME: 15:22:11; OriginalSymbolOrigin: (2540,10160); ADSCNVFLAG: ON; CHIPSIZE: D35xL30; MAXGCOUNT: 1; SIZECODESMD: DIP
C53 C54 C57-C60 C62 C64-C66 C70-C74 C77 C81 C82 = C_Dup1: OriginalSymbolOrigin: (2540,7620); COMP: PRT_52; MAXGCOUNT: 1; SAVECOUNT: 0
C55 C56 = C_Dup1: OriginalSymbolOrigin: (2540,7620); COMP: PRT_46; MAXGCOUNT: 1; SAVECOUNT: 0
C61 = C_Dup1: SQ_PART_MODEL: CON_47N; OriginalSymbolOrigin: (2540,7620); COMP: PRT_52; MAXGCOUNT: 1; ADSCNVFLAG: ON; ADSCOMPONENTNAME: C_1005; SAVECOUNT: 0
C63 = C_Dup1: OriginalSymbolOrigin: (2540,7620); COMP: PRT_52; OLDCOMPONENTID: 99; MAXGCOUNT: 1; SAVECOUNT: 0
C67 = C_Dup1: OriginalSymbolOrigin: (2540,7620); COMP: PRT_51; MAXGCOUNT: 1; SAVECOUNT: 0
C68 = C_Dup1: SQ_PART_MODEL: CON_100N; OriginalSymbolOrigin: (2540,7620); COMP: PRT_52; MAXGCOUNT: 1; ADSCNVFLAG: ON; ADSCOMPONENTNAME: C_1005; SAVECOUNT: 0
C69 = C_Dup1: OriginalSymbolOrigin: (2540,7620); COMP: PRT_48; SAVECOUNT: 0
C75 = C_Dup1: OriginalSymbolOrigin: (2540,7620); COMP: PRT_48; MAXGCOUNT: 1; SAVECOUNT: 0
C76 = C_Dup1: OriginalSymbolOrigin: (2540,7620); COMP: PRT_52; CHIPSIZE: 2012; MAXGCOUNT: 1; SAVECOUNT: 0
C78 C79 = C4532: TIME: 10:25:11; UPDATEUSER: t4887876; UPDATETIME: 06:36:44; SAVECOUNT: 15; VAL3: xx獸¦鋗ﾓ; OriginalSymbolOrigin: (2540,7620)
D51-D54 = CRG04A: SAVEAREA0: -4630,-153,17114,13055; TIME: 14:49:55; UPDATEUSER: t6860224; UPDATETIME: 10:39:47; SAVECOUNT: 14; MAXV: 600V; MAXI: 1A; OriginalSymbolOrigin: (5080,5080); USERCOMPTEXT2: 600V,1A; MAXGCOUNT: 1
D55 = GSIB2580: SAVECOUNT: 9; SAVEAREA0: -7762,-358,32649,26224; TIME: 10:09:47; UPDATEUSER: t4887876; UPDATETIME: 16:12:06; VAL2: 25A; OriginalSymbolOrigin: (0,25400); MAXGCOUNT: 1
D56 D57 = SBD_TO-220-2L: SAVEAREA0: -4630,-153,17114,13055; TIME: 14:49:55; UPDATEUSER: t4887876; UPDATETIME: 14:13:36; SAVECOUNT: 13; VAL2: R・&¦#ﾐ{¦; OriginalSymbolOrigin: (5080,5080); MAXGCOUNT: 1
D58 D61-D63 D66 = D_Dup1: SAVEAREA0: -225,-91,12804,7836; SAVECOUNT: 3; TIME: 14:49:55; UPDATEUSER: 19870035; UPDATETIME: 14:20:16; OriginalSymbolOrigin: (5080,5080); USERCOMPTEXT2: 80V,0.1A; COMP: PRT_27; MAXGCOUNT: 1
D59 D60 D64 D65 = CUHS15S30: SAVEAREA0: -4630,-153,17114,13055; TIME: 14:49:55; UPDATEUSER: t4887876; UPDATETIME: 17:19:09; SAVECOUNT: 10; OriginalSymbolOrigin: (5080,5080); USERCOMPTEXT2: 30V,1.5A; MAXGCOUNT: 1
D67 = D_Dup1: SAVEAREA0: -225,-91,12804,7836; SAVECOUNT: 3; TIME: 14:49:55; UPDATEUSER: 19870035; UPDATETIME: 14:20:16; OriginalSymbolOrigin: (5080,5080); USERCOMPTEXT2: 80V,0.1A; COMP: PRT_27; MAXGCOUNT: 1; ADSCNVFLAG: ON; ADSCOMPONENTNAME: D_D
D68 = ZD: SAVEAREA0: -4630,-153,17114,13055; TIME: 14:49:55; UPDATEUSER: fukuda-y; UPDATETIME: 08:18:42; SAVECOUNT: 6; OriginalSymbolOrigin: (5080,5080); COMP: PRT_6; MAXGCOUNT: 1
DP1 DP51 DP53 DP55 DP57 DP58 = TP: TIME: 16:12:21; UPDATEUSER: fukuda-y; UPDATETIME: 16:18:11; SAVECOUNT: 2; SAVEAREA0: -242,-92,12810,7836; OriginalSymbolOrigin: (0,7620); COMP: PRT_44
DP52 DP54 DP56 DP60 DP61 = TP: TIME: 16:12:21; UPDATEUSER: fukuda-y; UPDATETIME: 16:18:11; SAVECOUNT: 2; SAVEAREA0: -242,-92,12810,7836; OriginalSymbolOrigin: (0,7620); COMP: DTP815
DP59 = TP: TIME: 16:12:21; UPDATEUSER: fukuda-y; UPDATETIME: 16:18:11; SAVECOUNT: 2; SAVEAREA0: -242,-92,12810,7836; OriginalSymbolOrigin: (0,7620); COMP: PRT_49
IC51 = L27524: SAVEAREA0: -24347,-591,50370,48694; SAVECOUNT: 22; TIME: 15:02:55; UPDATEUSER: cae; UPDATETIME: 14:54:38; OriginalSymbolOrigin: (7620,45720); VAL3: UCC27524AD; COMP: PRT_63
IC52 = L28070: SAVEAREA0: -12344,-1037,78634,87348; SAVECOUNT: 29; TIME: 15:02:55; UPDATEUSER: cae; UPDATETIME: 14:36:12; OriginalSymbolOrigin: (7620,83820); VAL3: UCC28070A; COMP: PRT_59
L51 L52 = L: OriginalSymbolOrigin: (2540,5080); COMP: PRT_41; MAXGCOUNT: 1; SAVECOUNT: 0
L53 L54 = L: OriginalSymbolOrigin: (2540,5080); COMP: PRT_30; SAVECOUNT: 0
Q51 Q52 = TK125N60Z1: SAVECOUNT: 12; SAVEAREA0: -7027,-292,21786,15988; TIME: 18:23:27; UPDATEUSER: t6860224; OriginalSymbolOrigin: (5080,12700); MAXGCOUNT: 1
R51 R53 R56 R59 R61 R64 R65 R67 R69 R74 R76 R79 R83 R85 R89-R91 R96 = R_Dup1: as R4 on sheet 1
R52 R60 = R_Dup1: VAL2: 500mW; OriginalSymbolOrigin: (5080,5080); COMP: PRT_23; SAVECOUNT: 0
R54 R55 R62 R63 = R_Dup1: VAL2: 250mW; OriginalSymbolOrigin: (5080,5080); COMP: R2012; CHIPSIZE: 3216; MAXGCOUNT: 1; SAVECOUNT: 0
R57 = R_Dup1: SQ_PART_MODEL: RES_1.74K; VAL2: 63mW; OriginalSymbolOrigin: (5080,5080); COMP: GDM010004481; CHIPSIZE: 1608; MAXGCOUNT: 1; ADSCNVFLAG: ON; ADSCOMPONENTNAME: R_1608; SAVECOUNT: 0
R58 R66 = R_Dup1: VAL2: 63mW; OriginalSymbolOrigin: (5080,5080); MAXGCOUNT: 1; CHIPSIZE: 1608; COMP: GDM010004481; SAVECOUNT: 0
R68 = R_Dup1: VAL2: 63mW; OriginalSymbolOrigin: (5080,5080); COMP: GDM010004481; CHIPSIZE: 1608; OLDCOMPONENTID: 100; MAXGCOUNT: 1; SAVECOUNT: 0
R70-R72 R92-R94 = R_Dup1: VAL2: 250mW; OriginalSymbolOrigin: (5080,5080); COMP: PRT_5; CHIPSIZE: 1608; MAXGCOUNT: 1; SAVECOUNT: 0
R73 R77 R81 R87 R88 R95 = R_Dup1: VAL2: 63mW; OriginalSymbolOrigin: (5080,5080); MAXGCOUNT: 1; COMP: GDM010004481; CHIPSIZE: 1608; SAVECOUNT: 0
R78 R82 R84 = R_Dup1: VAL2: 63mW; OriginalSymbolOrigin: (5080,5080); COMP: GDM010004481; CHIPSIZE: 1608; SAVECOUNT: 0
R80 R86 = R_Dup1: OriginalSymbolOrigin: (5080,5080); COMP: GDM010004481; CHIPSIZE: 1608; SAVECOUNT: 0
R97 R98 = R_Dup1: VAL2: 63mW; OriginalSymbolOrigin: (5080,5080); COMP: GDM010004481; CHIPSIZE: 1608; MAXGCOUNT: 1
T51 T52 = T2Q: OriginalSymbolOrigin: (5080,20320); COMP: PRT_7; MAXGCOUNT: 1; SAVECOUNT: 0
U?#2 = WAKU_A3_TDSC_PSDEV_LOCAL: PLOTTIME: HH:MM; SAVEAREA0: -311037,-554865,914355,115662; TIME: 10:19:22; UPDATEUSER: t5459927; UPDATETIME: 17:59:49; SAVECOUNT: 3; ZONEOFFSETX: 36; ZONEOFFSETY: -24; OriginalSymbolOrigin: (0,434340); SHTSAVECOUNT: 144; PAGENUMBER: 2; DESIGNED: TOSHIBA

## Sheet 3.SchDoc
size 599 x 434 mm
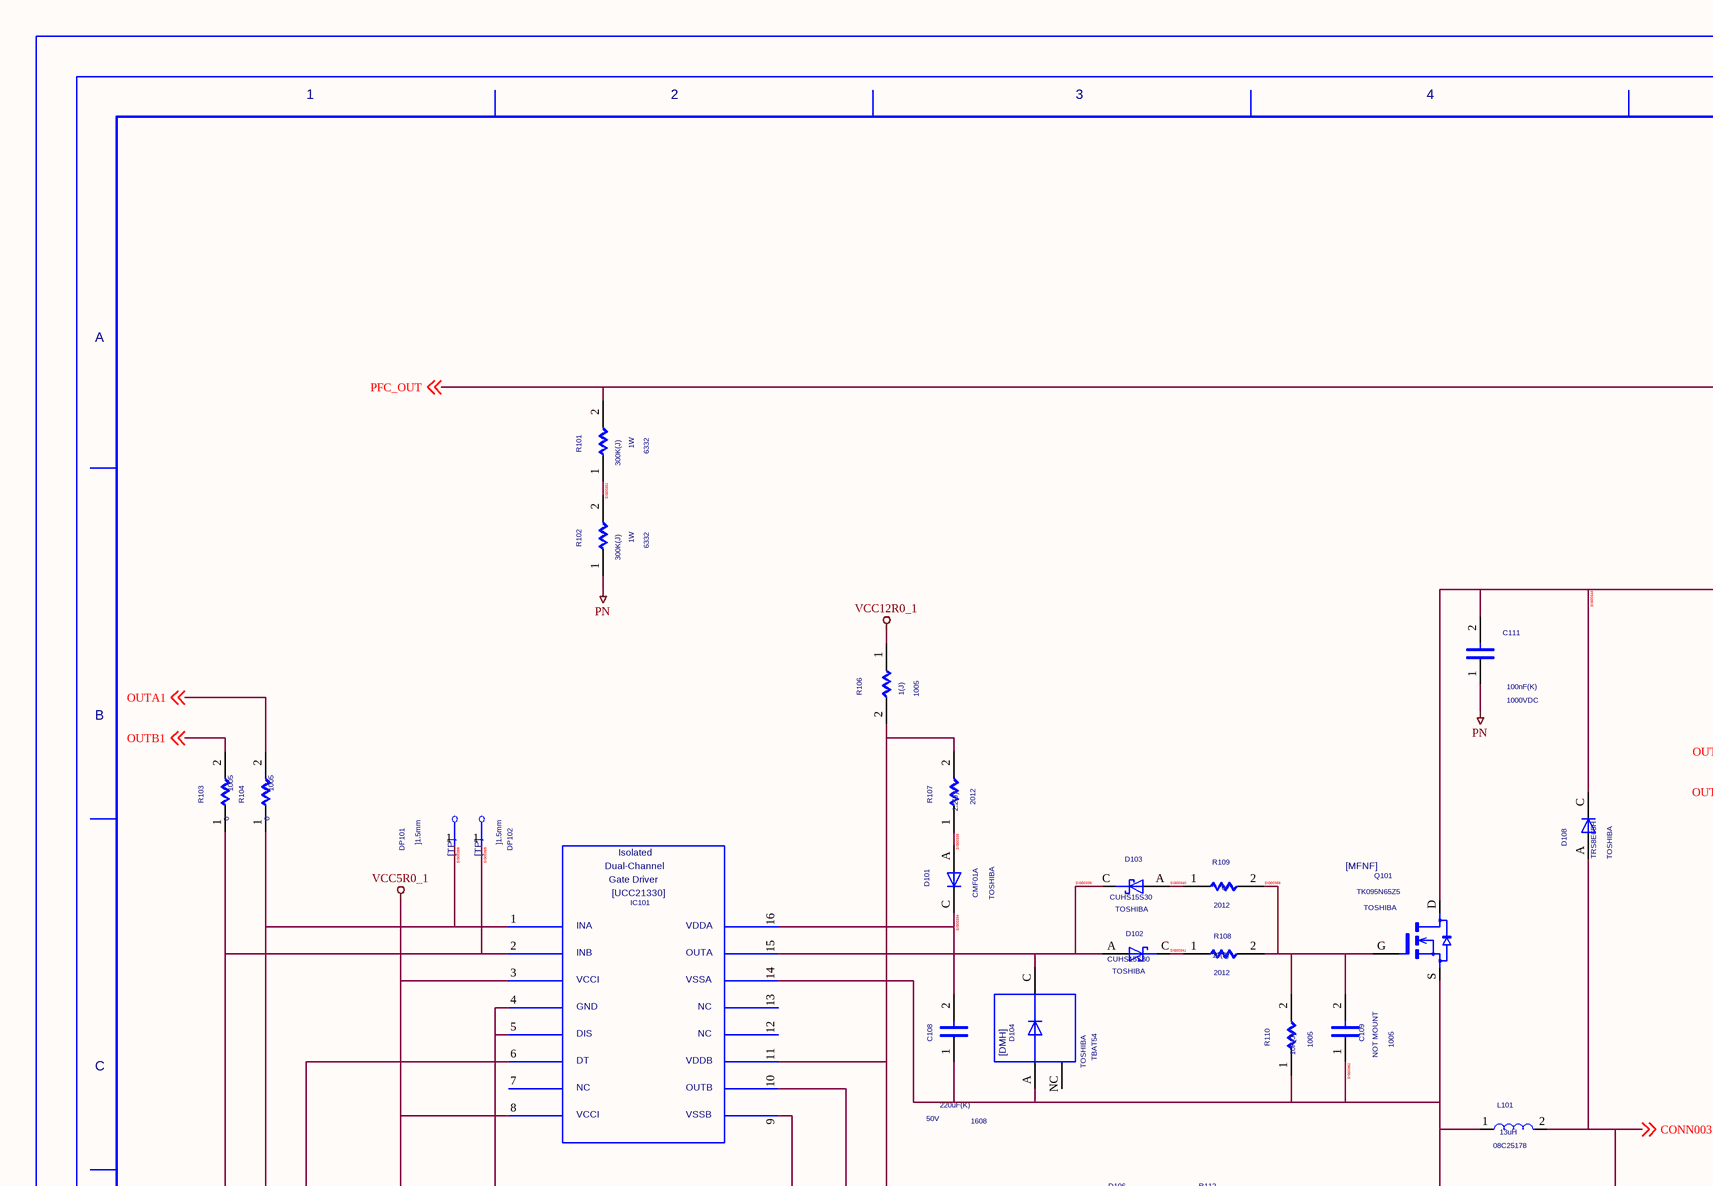
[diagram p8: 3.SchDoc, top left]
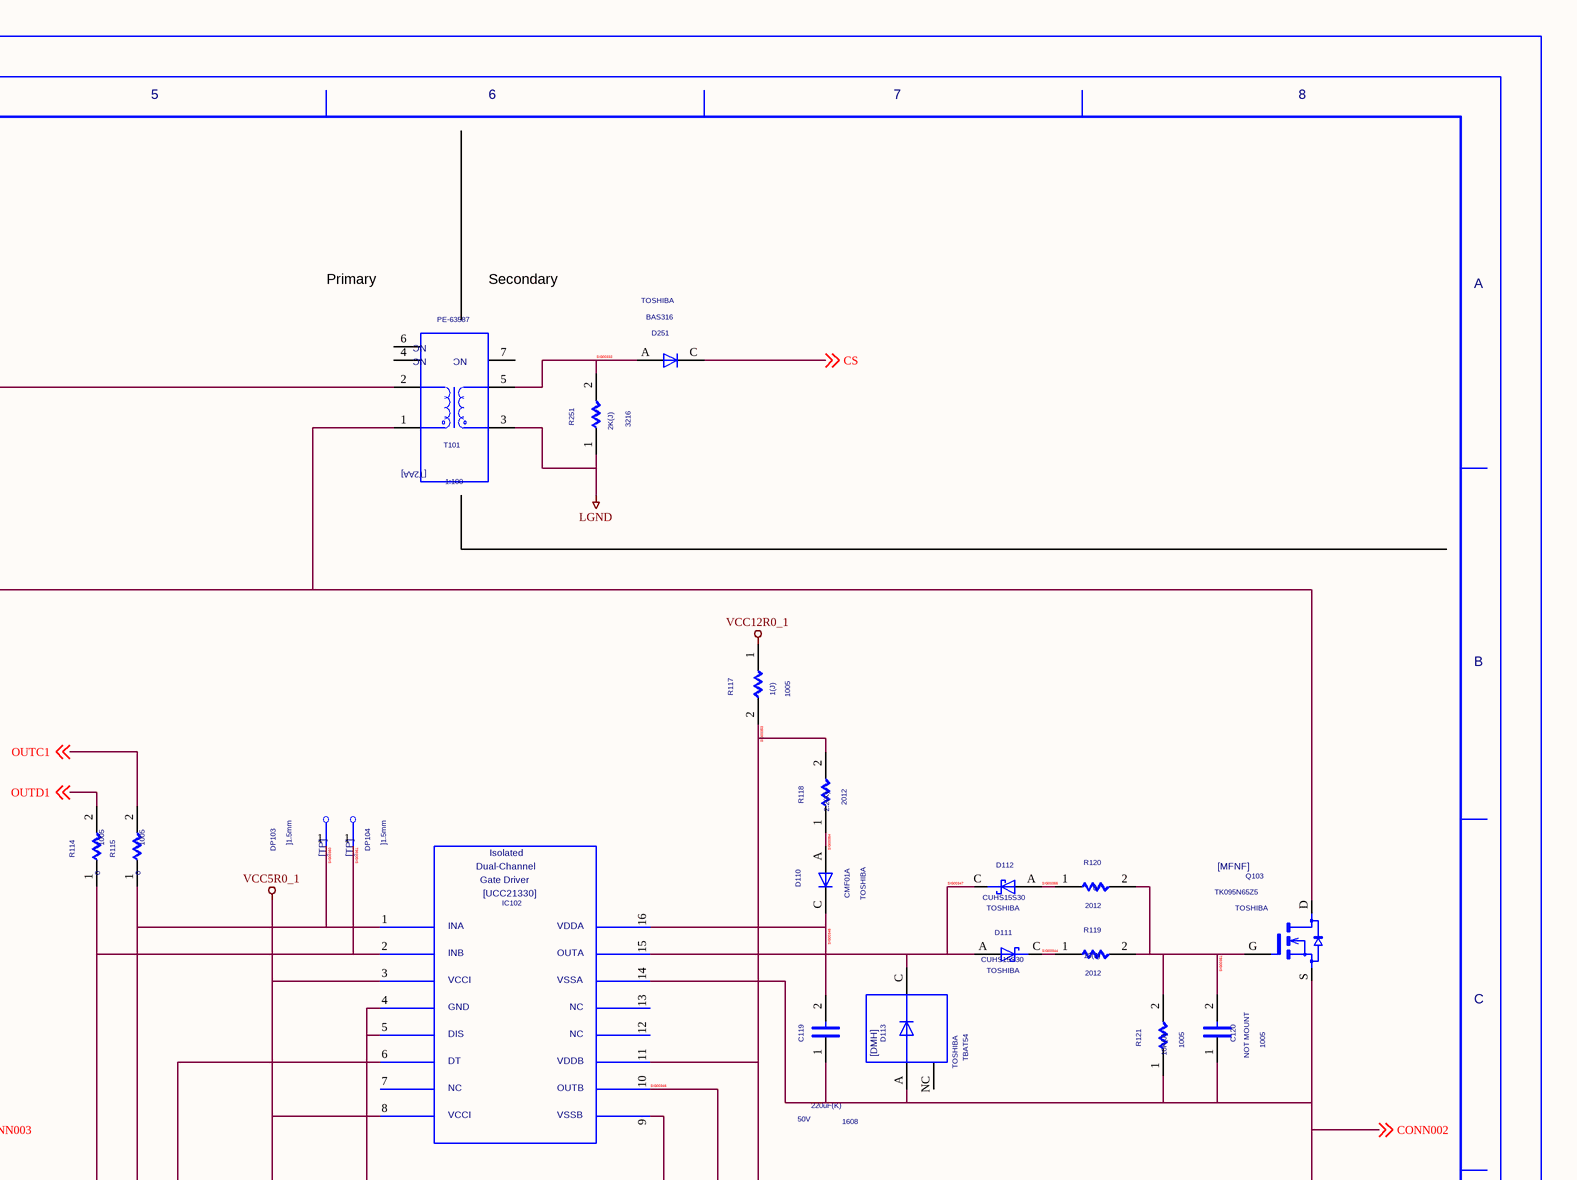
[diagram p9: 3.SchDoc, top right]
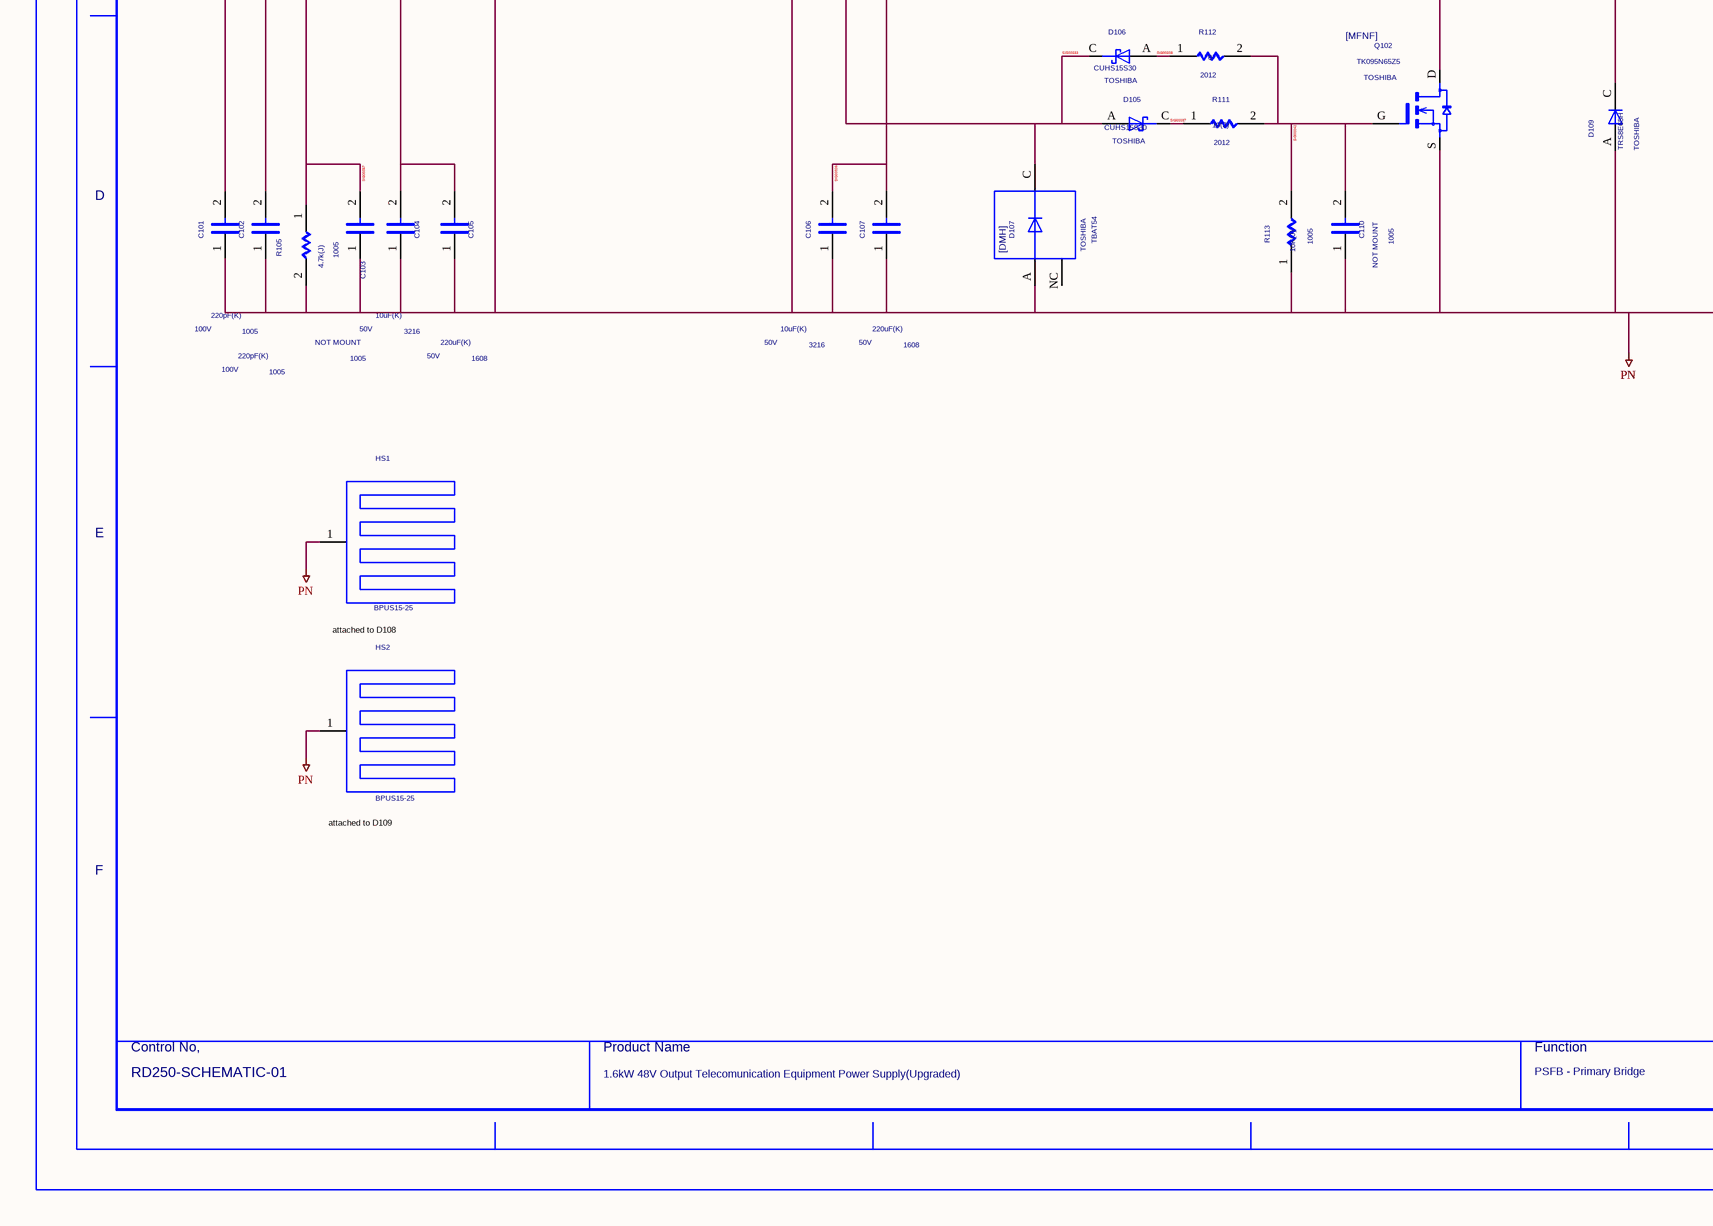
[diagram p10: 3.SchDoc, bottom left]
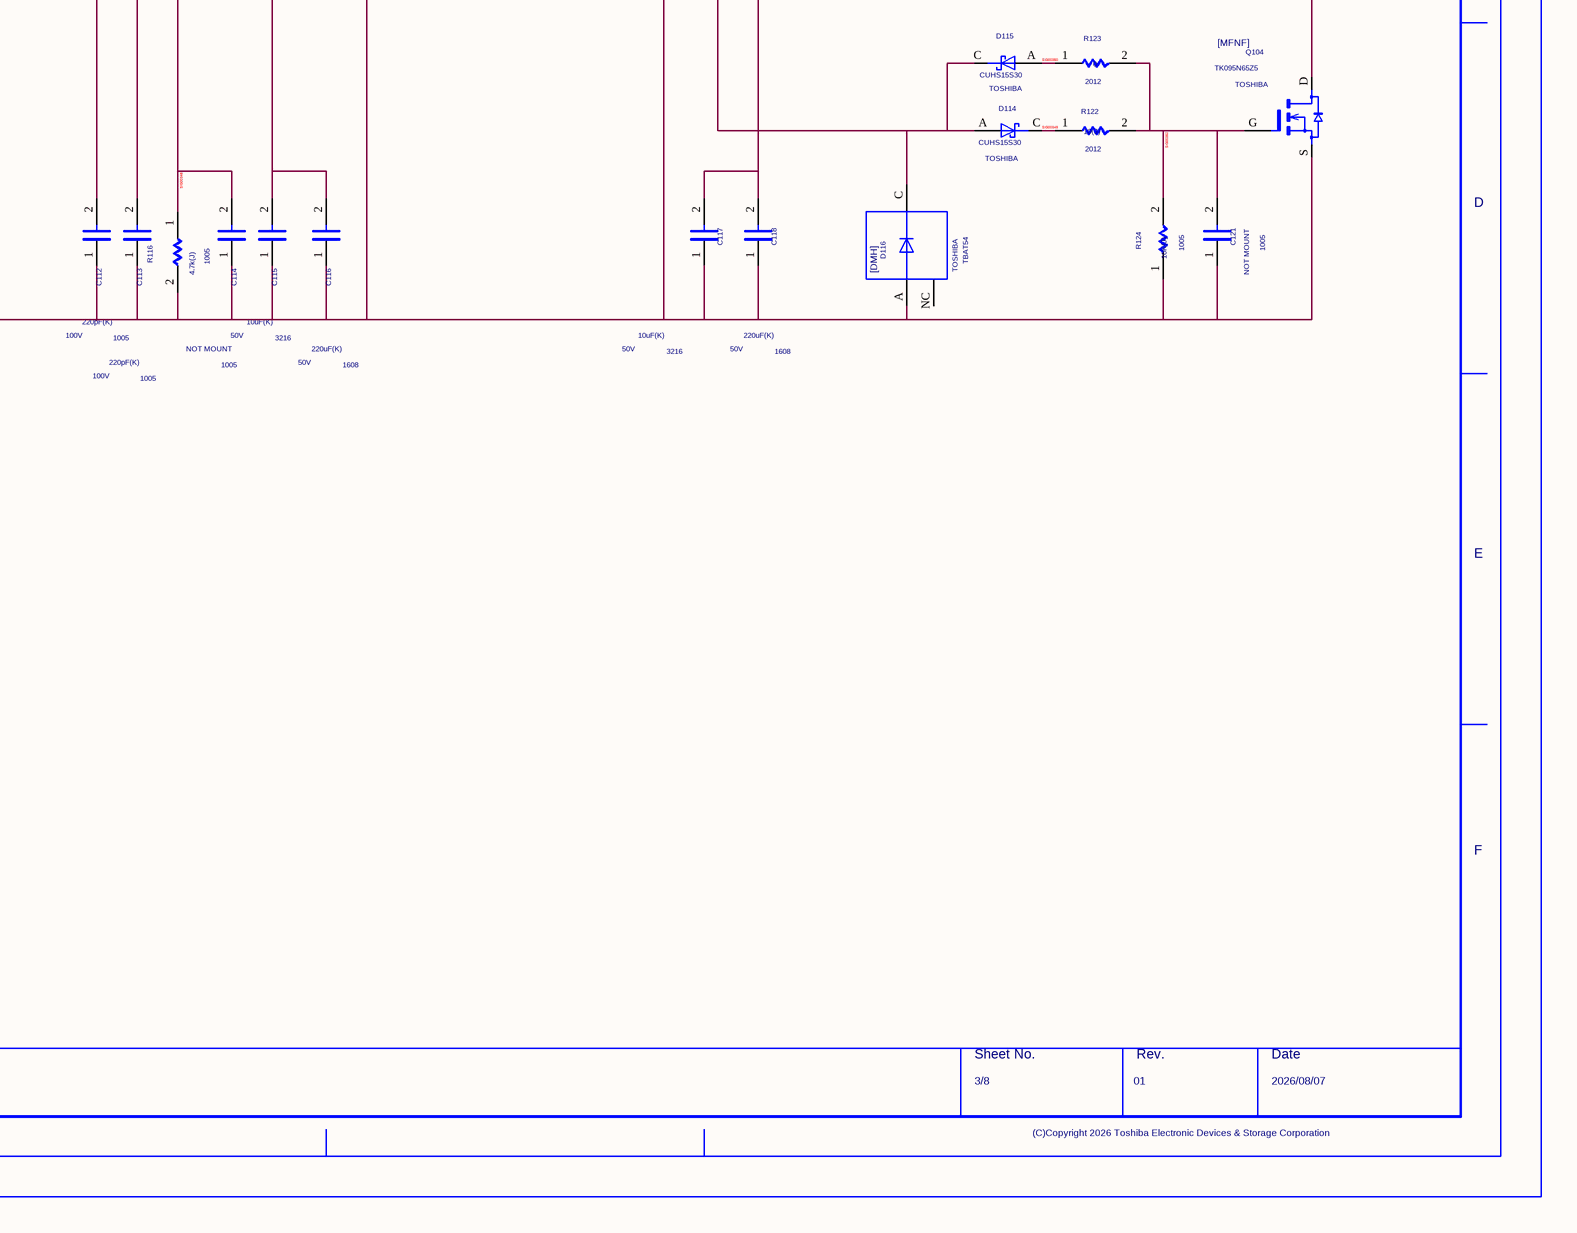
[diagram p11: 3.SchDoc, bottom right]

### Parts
(Parts that share a designator on the sheet are numbered #1, #2 ... from top to bottom, then left to right.)
C101  VAL1: 220pF(K)  VAL2: 100V  SIZECODESMD: 1005  (hidden comment: C)
C102  VAL1: 220pF(K)  VAL2: 100V  SIZECODESMD: 1005  (hidden comment: C)
C103  NOTMOUNT: NOT MOUNT  SIZECODESMD: 1005  (hidden comment: C)
C104  VAL1: 10uF(K)  VAL2: 50V  SIZECODESMD: 3216  (hidden comment: C)
C105  VAL1: 220uF(K)  VAL2: 50V  SIZECODESMD: 1608  (hidden comment: C1608)
C106  VAL1: 10uF(K)  VAL2: 50V  SIZECODESMD: 3216  (hidden comment: C)
C107  VAL1: 220uF(K)  VAL2: 50V  SIZECODESMD: 1608  (hidden comment: C1608)
C108  VAL1: 220uF(K)  VAL2: 50V  SIZECODESMD: 1608  (hidden comment: C1608)
C109  NOTMOUNT: NOT MOUNT  SIZECODESMD: 1005  (hidden comment: C)
C110  NOTMOUNT: NOT MOUNT  SIZECODESMD: 1005  (hidden comment: C)
C111  VAL1: 100nF(K)  VAL2: 1000VDC  (hidden comment: RDER73A104K5B1H03B)
C112  VAL1: 220pF(K)  VAL2: 100V  SIZECODESMD: 1005  (hidden comment: C)
C113  VAL1: 220pF(K)  VAL2: 100V  SIZECODESMD: 1005  (hidden comment: C)
C114  NOTMOUNT: NOT MOUNT  SIZECODESMD: 1005  (hidden comment: C)
C115  VAL1: 10uF(K)  VAL2: 50V  SIZECODESMD: 3216  (hidden comment: C)
C116  VAL1: 220uF(K)  VAL2: 50V  SIZECODESMD: 1608  (hidden comment: C1608)
C117  VAL1: 10uF(K)  VAL2: 50V  SIZECODESMD: 3216  (hidden comment: C)
C118  VAL1: 220uF(K)  VAL2: 50V  SIZECODESMD: 1608  (hidden comment: C1608)
C119  VAL1: 220uF(K)  VAL2: 50V  SIZECODESMD: 1608  (hidden comment: C1608)
C120  NOTMOUNT: NOT MOUNT  SIZECODESMD: 1005  (hidden comment: C)
C121  NOTMOUNT: NOT MOUNT  SIZECODESMD: 1005  (hidden comment: C)
D101  USERCOMPTEXT3: TOSHIBA  VAL3: CMF01A  (hidden comment: D)
D102  USERCOMPTEXT3: TOSHIBA  (hidden comment: CUHS15S30)
D103  USERCOMPTEXT3: TOSHIBA  (hidden comment: CUHS15S30)
D104  USERCOMPTEXT3: TOSHIBA  VAL3: TBAT54  (hidden comment: DMH)
D105  USERCOMPTEXT3: TOSHIBA  (hidden comment: CUHS15S30)
D106  USERCOMPTEXT3: TOSHIBA  (hidden comment: CUHS15S30)
D107  USERCOMPTEXT3: TOSHIBA  VAL3: TBAT54  (hidden comment: DMH)
D108  VAL3: TRS8E65H  USERCOMPTEXT3: TOSHIBA  (hidden comment: TRS8E65F)
D109  VAL3: TRS8E65H  USERCOMPTEXT3: TOSHIBA  (hidden comment: TRS8E65F)
D110  USERCOMPTEXT3: TOSHIBA  VAL3: CMF01A  (hidden comment: D)
D111  USERCOMPTEXT3: TOSHIBA  (hidden comment: CUHS15S30)
D112  USERCOMPTEXT3: TOSHIBA  (hidden comment: CUHS15S30)
D113  USERCOMPTEXT3: TOSHIBA  VAL3: TBAT54  (hidden comment: DMH)
D114  USERCOMPTEXT3: TOSHIBA  (hidden comment: CUHS15S30)
D115  USERCOMPTEXT3: TOSHIBA  (hidden comment: CUHS15S30)
D116  USERCOMPTEXT3: TOSHIBA  VAL3: TBAT54  (hidden comment: DMH)
D251  USERCOMPTEXT3: TOSHIBA  VAL3: BAS316  (hidden comment: D)
DP101  USERCOMPTEXT1: ]1.5mm  (hidden comment: TP)
DP102  USERCOMPTEXT1: ]1.5mm  (hidden comment: TP)
DP103  USERCOMPTEXT1: ]1.5mm  (hidden comment: TP)
DP104  USERCOMPTEXT1: ]1.5mm  (hidden comment: TP)
HS1  BPUS15-25
HS2  BPUS15-25
IC101  UCC21330  (value not drawn)
IC102  UCC21330  (value not drawn)
L101  VAL3: 08C25178  VAL1: 13uH  (hidden comment: TMSD-Y3001)
Q101  USERCOMPTEXT3: TOSHIBA  (hidden comment: TK095N65Z5)
Q102  USERCOMPTEXT3: TOSHIBA  (hidden comment: TK095N65Z5)
Q103  USERCOMPTEXT3: TOSHIBA  (hidden comment: TK095N65Z5)
Q104  USERCOMPTEXT3: TOSHIBA  (hidden comment: TK095N65Z5)
R101  VAL2: 1W  VAL1: 300K(J)  SIZECODESMD: 6332  (hidden comment: R)
R102  VAL2: 1W  VAL1: 300K(J)  SIZECODESMD: 6332  (hidden comment: R)
R103  VAL1: 0  SIZECODESMD: 1005  (hidden comment: R)
R104  VAL1: 0  SIZECODESMD: 1005  (hidden comment: R)
R105  VAL1: 4.7k(J)  SIZECODESMD: 1005  (hidden comment: R)
R106  VAL1: 1(J)  SIZECODESMD: 1005  (hidden comment: R)
R107  VAL1: 2.2(J)  SIZECODESMD: 2012  (hidden comment: R)
R108  VAL1: 10(J)  SIZECODESMD: 2012  (hidden comment: R)
R109  VAL1: 0  SIZECODESMD: 2012  (hidden comment: R)
R110  VAL1: 10K(J)  SIZECODESMD: 1005  (hidden comment: R)
R111  VAL1: 10(J)  SIZECODESMD: 2012  (hidden comment: R)
R112  VAL1: 0  SIZECODESMD: 2012  (hidden comment: R)
R113  VAL1: 10K(J)  SIZECODESMD: 1005  (hidden comment: R)
R114  VAL1: 0  SIZECODESMD: 1005  (hidden comment: R)
R115  VAL1: 0  SIZECODESMD: 1005  (hidden comment: R)
R116  VAL1: 4.7k(J)  SIZECODESMD: 1005  (hidden comment: R)
R117  VAL1: 1(J)  SIZECODESMD: 1005  (hidden comment: R)
R118  VAL1: 2.2(K)  SIZECODESMD: 2012  (hidden comment: R)
R119  VAL1: 10(J)  SIZECODESMD: 2012  (hidden comment: R)
R120  VAL1: 0  SIZECODESMD: 2012  (hidden comment: R)
R121  VAL1: 10K(J)  SIZECODESMD: 1005  (hidden comment: R)
R122  VAL1: 10(J)  SIZECODESMD: 2012  (hidden comment: R)
R123  VAL1: 0  SIZECODESMD: 2012  (hidden comment: R)
R124  VAL1: 10K(J)  SIZECODESMD: 1005  (hidden comment: R)
R251  VAL1: 2K(J)  SIZECODESMD: 3216  (hidden comment: R)
T101  VAL1: 1:100  VAL3: PE-63587  (hidden comment: T2AA)
U?#3  DATE: 2026/08/07  DRAWINGNUMBER: RD250-SCHEMATIC-01  TITLE: 1.6kW 48V Output Telecomunication / Equipment Power Supply(Upgraded)  FUNCTION: PSFB - Primary Bridge  SHEETNUMBER: 3/8  REVISION: 01  (hidden comment: WAKU_A3_TDSC_PSDEV_LOCAL)

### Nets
LGND: R251.1 T101.3
PN: C101.1 C102.1 C103.1 C104.1 C105.1 C106.1 C107.1 C110.1 C111.1 C112.1 C113.1 C114.1 C115.1 C116.1 C117.1 C118.1 C121.1 D107.A D109.A D116.A HS1.1 HS2.1 IC101.4 IC101.5 IC101.9 IC102.4 IC102.5 IC102.9 Q102.S Q104.S R102.1 R105.2 R113.1 R116.2 R124.1
VCC5R0_1: C104.2 C105.2 C115.2 C116.2 IC101.3 IC101.8 IC102.3 IC102.8
VCC12R0_1: R106.1 R117.1
CONN002: C119.1 C120.1 D113.A IC102.14 Q103.S Q104.D R121.1 ; off-sheet CONN002
CONN003: D108.A D109.C L101.2 ; off-sheet CONN003
CS: D251.C ; off-sheet CS
OUTA1: R104.2 ; off-sheet OUTA1
OUTB1: R103.2 ; off-sheet OUTB1
OUTC1: R115.2 ; off-sheet OUTC1
OUTD1: R114.2 ; off-sheet OUTD1
PFC_OUT: R101.2 T101.2 ; off-sheet PFC_OUT
SIG00331: R101.1 R102.2
SIG00332: D251.A R251.2 T101.5
SIG00333: D105.A D106.C D107.C IC101.10
SIG00334: C108.2 D101.C IC101.16
SIG00335: D101.A R107.1
SIG00336: C106.2 C107.2 IC101.11 R106.2 R107.2
SIG00337: D105.C R111.1
SIG00338: D106.A R112.1
SIG00339: D102.A D103.C D104.C IC101.15
SIG00340: D103.A R109.1
SIG00341: D102.C R108.1
SIG00342: C110.2 Q102.G R111.2 R112.2 R113.2
SIG00343: C111.2 D108.C Q101.D Q103.D T101.1
SIG00344: D111.C R119.1
SIG00345: C119.2 D110.C IC102.16
SIG00346: D114.A D115.C D116.C IC102.10
SIG00347: D111.A D112.C D113.C IC102.15
SIG00348: C114.2 IC102.6 R116.1
SIG00349: D114.C R122.1
SIG00350: D115.A R123.1
SIG00351: C120.2 Q103.G R119.2 R120.2 R121.2
SIG00352: C121.2 Q104.G R122.2 R123.2 R124.2
SIG00353: C117.2 C118.2 IC102.11 R117.2 R118.2
SIG00354: D110.A R118.1
SIG00355: D112.A R120.1
SIG00356: C109.2 Q101.G R108.2 R109.2 R110.2
SIG00357: C103.2 IC101.6 R105.1
SIG00358: C102.2 DP101.1 IC101.1 R104.1
SIG00359: C101.2 DP102.1 IC101.2 R103.1
SIG00360: C113.2 DP103.1 IC102.1 R115.1
SIG00361: C112.2 DP104.1 IC102.2 R114.1
SIG00362: C108.1 C109.1 D104.A IC101.14 L101.1 Q101.S Q102.D R110.1

Not connected (* = marked no-connect by the designer): D104 NC; D107 NC; D113 NC; D116 NC; IC101 7 12 13; IC102 7 12 13; T101 4 6 7

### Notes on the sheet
- Primary
- Secondary
- attached to D108
- attached to D109

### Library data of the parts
C101-C103 C109 C110 C112-C114 C120 C121 = C_Dup1: as C53 on sheet 2
C104 C106 C115 C117 = C_Dup1: as C55 on sheet 2
C105 C107 C108 C116 C118 C119 = C1608: SQ_PART_MODEL: CON_220N; TIME: 10:25:11; UPDATEUSER: t4887876; UPDATETIME: 06:19:09; SAVECOUNT: 10; VAL3: xx獸¦鋗ﾓ; OriginalSymbolOrigin: (2540,7620); CHIPSIZE: 1005; MAXGCOUNT: 1; ADSCNVFLAG: ON; ADSCOMPONENTNAME: C_1005
C111 = RDER73A104K5B1H03B: SQ_PART_MODEL: CON_100N; OUMEPARTTYPE2: C; TIME: 18:04:40; UPDATEUSER: t4887876; UPDATETIME: 14:18:01; SAVECOUNT: 7; OriginalSymbolOrigin: (2540,7620); MAXGCOUNT: 1; ADSCNVFLAG: ON; ADSCOMPONENTNAME: C_4532
D101 D110 = D_Dup1: SAVEAREA0: -225,-91,12804,7836; SAVECOUNT: 3; TIME: 14:49:55; UPDATEUSER: 19870035; UPDATETIME: 14:20:16; OriginalSymbolOrigin: (5080,5080); USERCOMPTEXT2: 600V,2A; COMP: PRT_14; MAXGCOUNT: 1
D102 D103 D105 D106 D111 D112 D114 D115 = CUHS15S30: SAVEAREA0: -4630,-153,17114,13055; TIME: 14:49:55; UPDATEUSER: t4887876; UPDATETIME: 17:19:09; SAVECOUNT: 10; OriginalSymbolOrigin: (5080,5080); USERCOMPTEXT2: 30V,1.5A
D104 D107 D113 D116 = DMH: SAVEAREA0: -4931,-287,27399,20979; TIME: 08:58:08; UPDATEUSER: kishi-s; UPDATETIME: 09:01:52; SAVECOUNT: 2; OriginalSymbolOrigin: (5080,17780); USERCOMPTEXT2: 30V,0.2A; COMP: PRT_25
D108 D109 = TRS8E65F: SAVEAREA0: -225,-91,12804,7836; SAVECOUNT: 5; TIME: 14:49:55; UPDATEUSER: t6860224; UPDATETIME: 17:57:03; OriginalSymbolOrigin: (5080,5080); USERCOMPTEXT2: 600V,2A; MAXGCOUNT: 1
D251 = D_Dup1: as D1 on sheet 1
DP101-DP104 = TP: as DP52 on sheet 2
HS1 HS2 = BPUS15-25: TIME: 14:03:26; UPDATEUSER: t4887876; UPDATETIME: 09:27:54; SAVECOUNT: 67; SAVEAREA0: -22025,-9177,43954,39124; VAL2: black anodizing; OriginalSymbolOrigin: (5080,22860)
IC101 = UCC21330: SAVEAREA0: -23586,-777,74646,64019; SAVECOUNT: 95; TIME: 14:04:55; UPDATEUSER: t6860224; UPDATETIME: 14:44:07; OriginalSymbolOrigin: (-2540,55880); VAL3: UCC21330BDR
IC102 = UCC21330_Dup1: SAVEAREA0: -23586,-777,74646,64019; SAVECOUNT: 94; TIME: 14:04:55; UPDATEUSER: t6860224; UPDATETIME: 14:44:07; OriginalSymbolOrigin: (-2540,55880); VAL3: UCC21330BDR
L101 = TMSD-Y3001: TIME: 11:29:15; UPDATEUSER: t4887876; UPDATETIME: 13:47:51; SAVECOUNT: 2; VAL2: (Rated Current/Idc=0A); OriginalSymbolOrigin: (2540,5080)
Q101-Q104 = TK095N65Z5: SAVECOUNT: 12; SAVEAREA0: -7027,-292,21786,15988; TIME: 18:24:15; UPDATEUSER: t6860224; OriginalSymbolOrigin: (5080,12700)
R101 R102 = R: SQ_PART_MODEL: RES_47K; OriginalSymbolOrigin: (5080,5080); MAXGCOUNT: 1; ADSCNVFLAG: ON; ADSCOMPONENTNAME: R_6332; COMP: GDM010001640; VAL3: RK73B3ATTE304J; CHIPSIZE: 6432; SAVECOUNT: 0
R103 R104 R114 R115 = R_Dup1: as R97 on sheet 2
R105 R106 R110 R113 R116 R117 R121 R124 = R_Dup1: as R4 on sheet 1
R107 R118 = R_Dup1: VAL2: 125mW; OriginalSymbolOrigin: (5080,5080); COMP: R2012; CHIPSIZE: 3216; MAXGCOUNT: 1; SAVECOUNT: 0
R108 R111 R119 R122 = R_Dup1: VAL2: 500mW; OriginalSymbolOrigin: (5080,5080); COMP: R2012; CHIPSIZE: 3216; MAXGCOUNT: 1; SAVECOUNT: 0
R109 R112 R120 R123 = R_Dup1: VAL2: 500mW; OriginalSymbolOrigin: (5080,5080); COMP: R2012; CHIPSIZE: 3216; MAXGCOUNT: 1
R251 = R_Dup1: SQ_PART_MODEL: RES_4.87K; VAL2: 250mW; OriginalSymbolOrigin: (5080,5080); COMP: PRT_5; CHIPSIZE: 1608; MAXGCOUNT: 1; ADSCNVFLAG: ON; ADSCOMPONENTNAME: R_3216; SAVECOUNT: 0
T101 = T2AA: TIME: 11:34:46; UPDATEUSER: t4887876; UPDATETIME: 16:34:34; SAVECOUNT: 11; SAVEAREA0: -20981,-344,43891,33349; OriginalSymbolOrigin: (5080,30480); COMP: PRT_65; MAXGCOUNT: 1
U?#3 = WAKU_A3_TDSC_PSDEV_LOCAL: PLOTTIME: HH:MM; SAVEAREA0: -311037,-554865,914355,115662; TIME: 15:47:55; UPDATEUSER: t5459927; UPDATETIME: 17:59:50; SAVECOUNT: 3; ZONEOFFSETX: 36; ZONEOFFSETY: -24; OriginalSymbolOrigin: (0,434340); SHTSAVECOUNT: 136; DESIGNED: TOSHIBA

## Sheet 4.SchDoc
size 599 x 434 mm
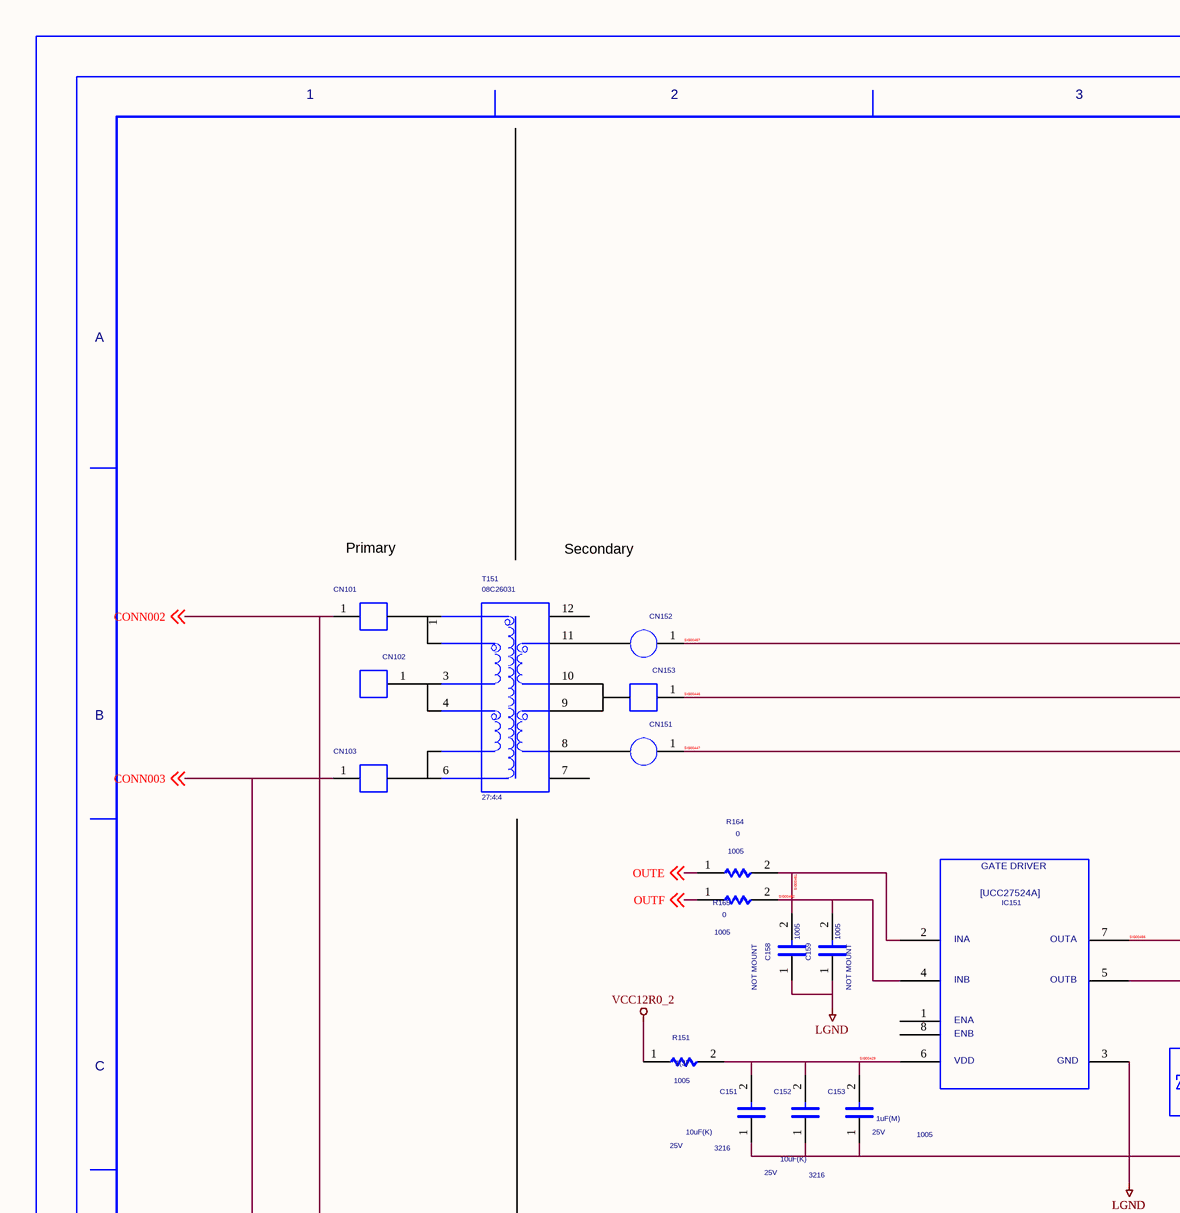
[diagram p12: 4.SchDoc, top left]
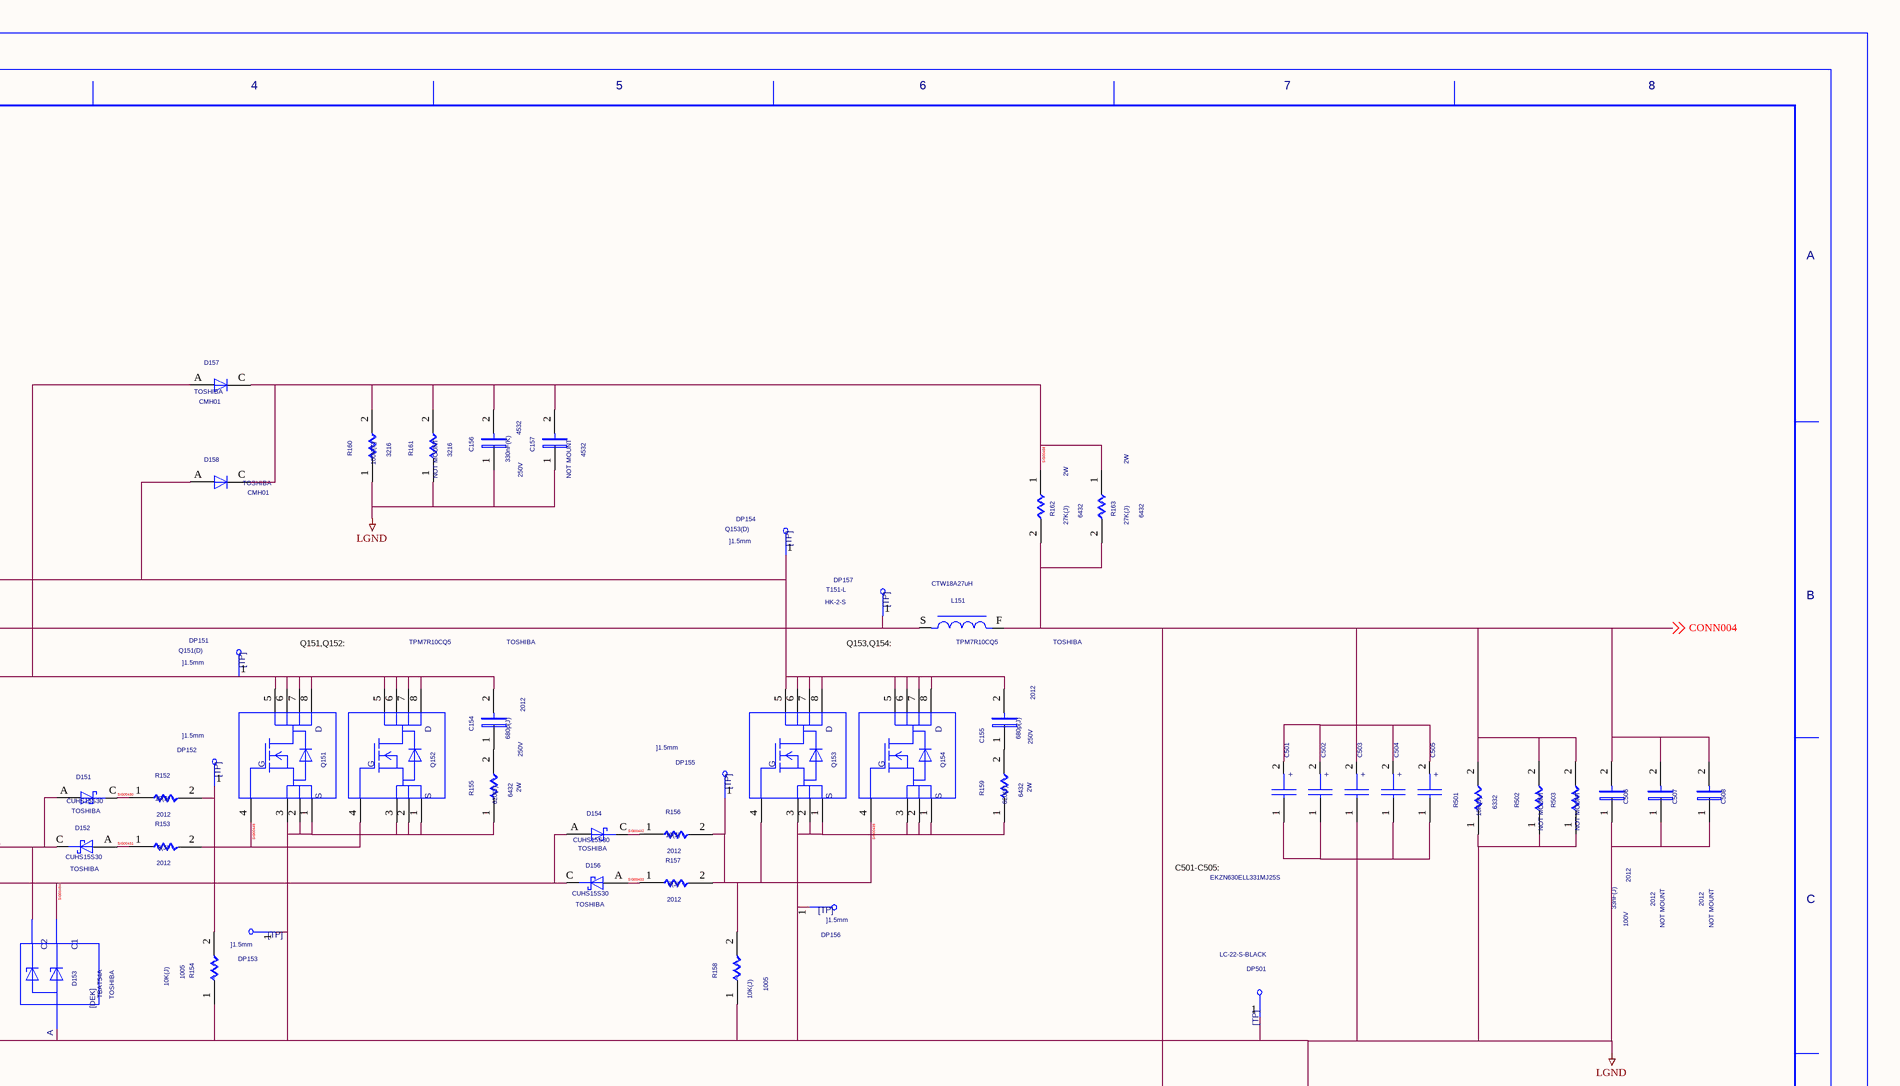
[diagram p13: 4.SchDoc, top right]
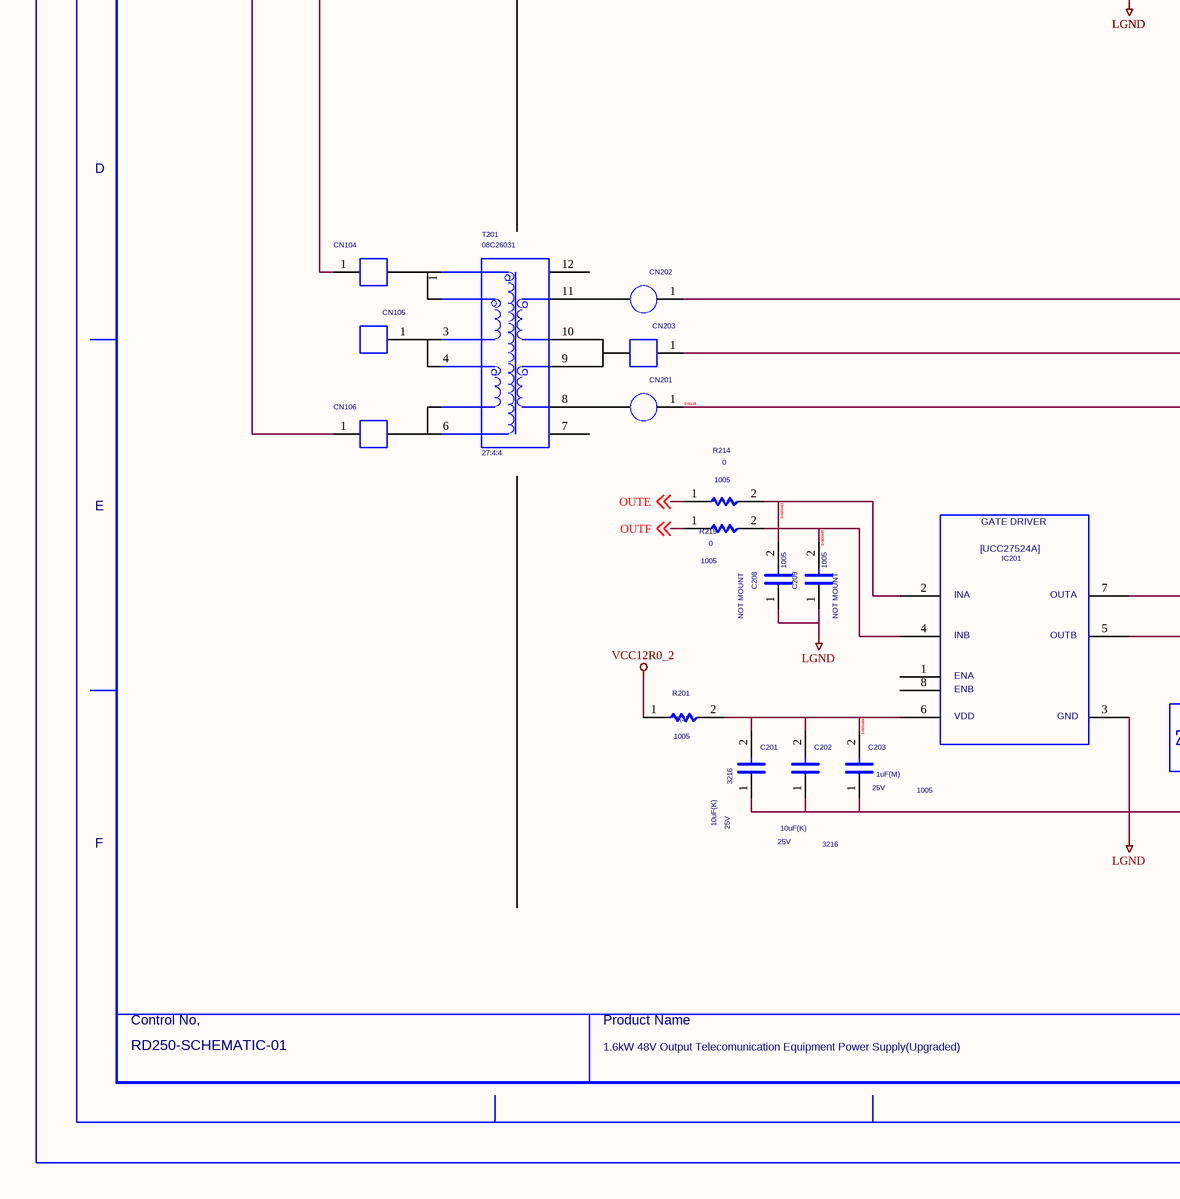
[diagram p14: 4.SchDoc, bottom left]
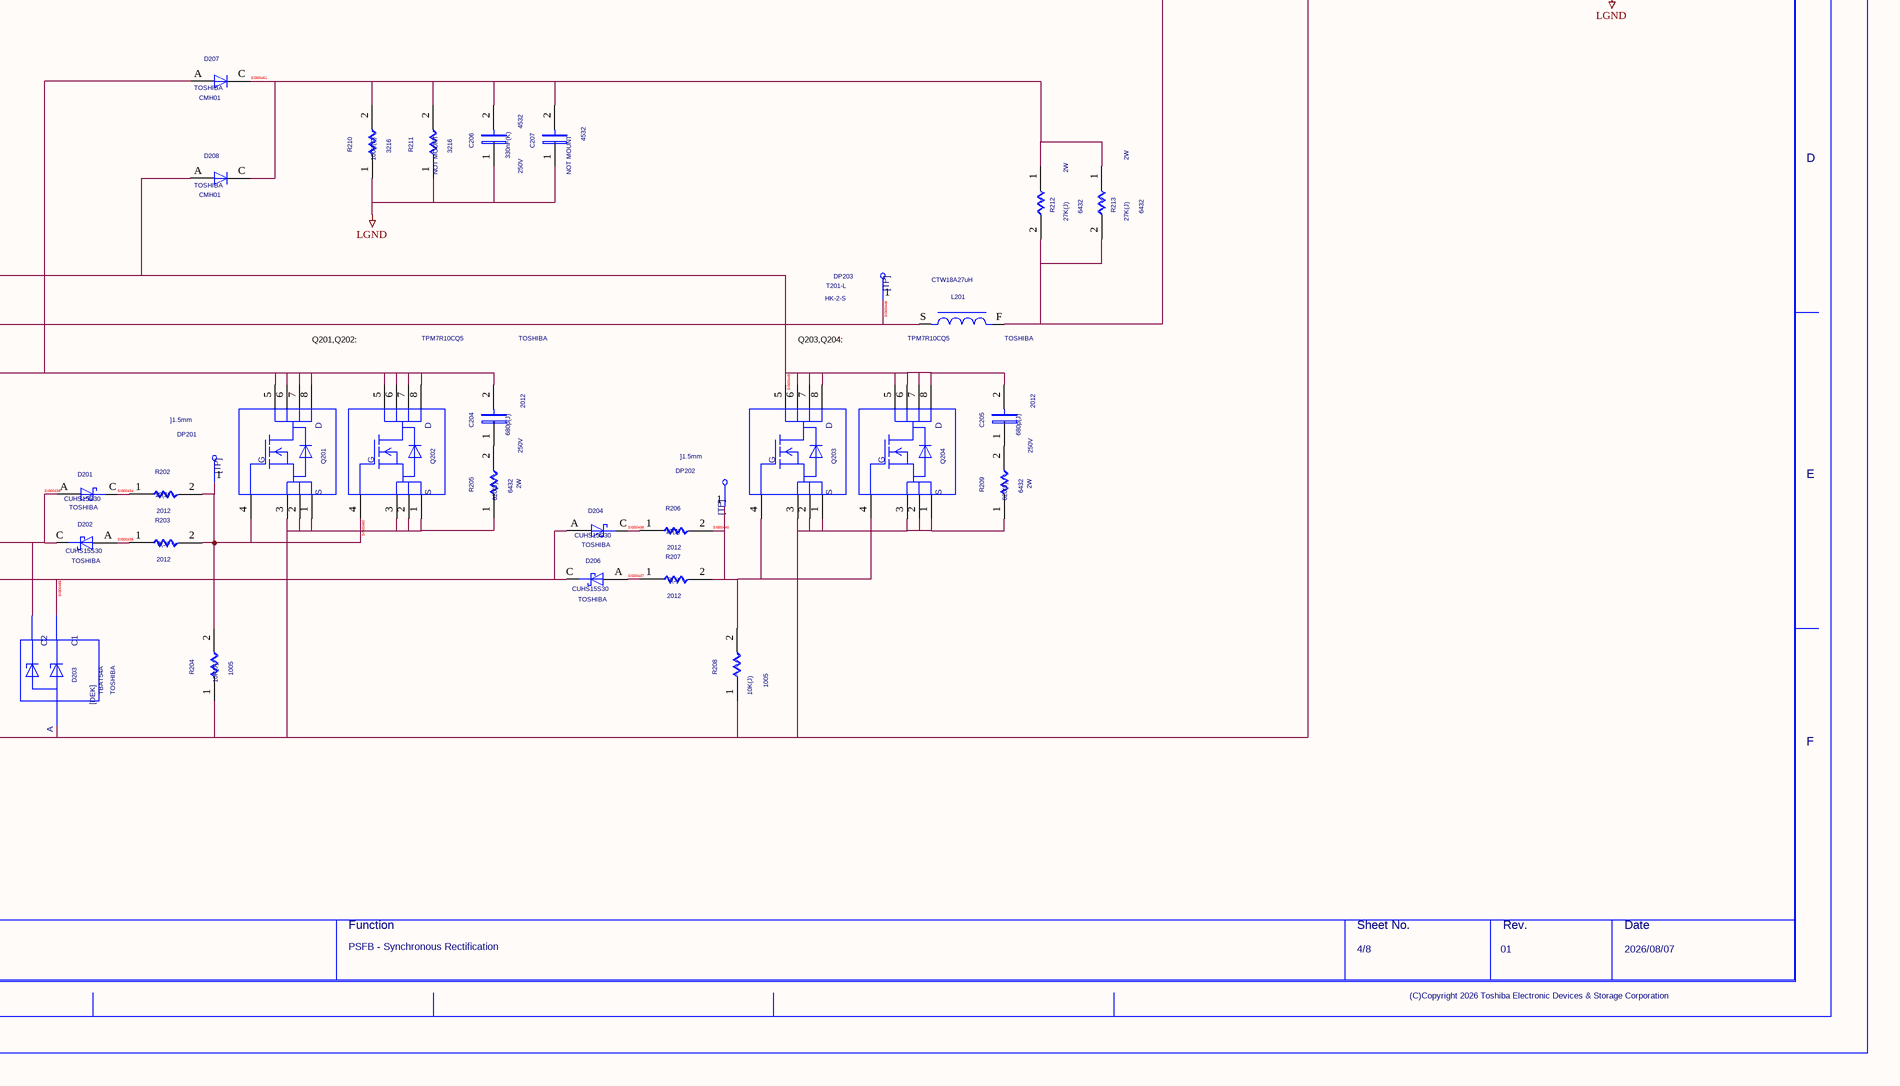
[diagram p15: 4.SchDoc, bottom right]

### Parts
(Parts that share a designator on the sheet are numbered #1, #2 ... from top to bottom, then left to right.)
C151  VAL1: 10uF(K)  VAL2: 25V  SIZECODESMD: 3216  (hidden comment: C)
C152  VAL1: 10uF(K)  VAL2: 25V  SIZECODESMD: 3216  (hidden comment: C)
C153  VAL1: 1uF(M)  VAL2: 25V  SIZECODESMD: 1005  (hidden comment: C)
C154  VAL1: 680p(J)  VAL2: 250V  SIZECODESMD: 2012  (hidden comment: GRM21BC71E106KE01)
C155  VAL1: 680p(J)  VAL2: 250V  SIZECODESMD: 2012  (hidden comment: GRM21BC71E106KE01)
C156  VAL1: 330nF(K)  VAL2: 250V  SIZECODESMD: 4532  (hidden comment: C)
C157  NOTMOUNT: NOT MOUNT  SIZECODESMD: 4532  (hidden comment: C)
C158  NOTMOUNT: NOT MOUNT  SIZECODESMD: 1005  (hidden comment: C)
C159  NOTMOUNT: NOT MOUNT  SIZECODESMD: 1005  (hidden comment: C)
C201  VAL1: 10uF(K)  VAL2: 25V  SIZECODESMD: 3216  (hidden comment: C)
C202  VAL1: 10uF(K)  VAL2: 25V  SIZECODESMD: 3216  (hidden comment: C)
C203  VAL1: 1uF(M)  VAL2: 25V  SIZECODESMD: 1005  (hidden comment: C)
C204  VAL1: 680p(J)  VAL2: 250V  SIZECODESMD: 2012  (hidden comment: GRM21BC71E106KE01)
C205  VAL1: 680p(J)  VAL2: 250V  SIZECODESMD: 2012  (hidden comment: GRM21BC71E106KE01)
C206  VAL1: 330nF(K)  VAL2: 250V  SIZECODESMD: 4532  (hidden comment: C)
C207  NOTMOUNT: NOT MOUNT  SIZECODESMD: 4532  (hidden comment: C)
C208  NOTMOUNT: NOT MOUNT  SIZECODESMD: 1005  (hidden comment: C)
C209  NOTMOUNT: NOT MOUNT  SIZECODESMD: 1005  (hidden comment: C)
C501  VAL3: EKZN630ELL331MJ25S  (hidden comment: CP)
C502  CP  (value not drawn)
C503  CP  (value not drawn)
C504  CP  (value not drawn)
C505  CP  (value not drawn)
C506  VAL1: 33nF(J)  VAL2: 100V  SIZECODESMD: 2012  (hidden comment: GRM21BC71E106KE01)
C507  NOTMOUNT: NOT MOUNT  SIZECODESMD: 2012  (hidden comment: GRM21BC71E106KE01)
C508  NOTMOUNT: NOT MOUNT  SIZECODESMD: 2012  (hidden comment: GRM21BC71E106KE01)
CN101  Longhole_2R5-4R5  (value not drawn)
CN102  Longhole_2R5-4R5  (value not drawn)
CN103  Longhole_2R5-4R5  (value not drawn)
CN104  Longhole_2R5-4R5  (value not drawn)
CN105  Longhole_2R5-4R5  (value not drawn)
CN106  Longhole_2R5-4R5  (value not drawn)
CN151  TH_phi_3R5  (value not drawn)
CN152  TH_phi_3R5  (value not drawn)
CN153  Longhole_3R5-7R0  (value not drawn)
CN201  TH_phi_3R5  (value not drawn)
CN202  TH_phi_3R5  (value not drawn)
CN203  Longhole_3R5-7R0  (value not drawn)
D151  USERCOMPTEXT3: TOSHIBA  (hidden comment: CUHS15S30)
D152  USERCOMPTEXT3: TOSHIBA  (hidden comment: CUHS15S30)
D153  USERCOMPTEXT3: TOSHIBA  VAL3: TBAT54A  (hidden comment: DEK_RD244)
D154  USERCOMPTEXT3: TOSHIBA  (hidden comment: CUHS15S30)
D156  USERCOMPTEXT3: TOSHIBA  (hidden comment: CUHS15S30)
D157  USERCOMPTEXT3: TOSHIBA  VAL3: CMH01  (hidden comment: D)
D158  USERCOMPTEXT3: TOSHIBA  VAL3: CMH01  (hidden comment: D)
D201  USERCOMPTEXT3: TOSHIBA  (hidden comment: CUHS15S30)
D202  USERCOMPTEXT3: TOSHIBA  (hidden comment: CUHS15S30)
D203  USERCOMPTEXT3: TOSHIBA  VAL3: TBAT54A  (hidden comment: DEK_RD244)
D204  USERCOMPTEXT3: TOSHIBA  (hidden comment: CUHS15S30)
D206  USERCOMPTEXT3: TOSHIBA  (hidden comment: CUHS15S30)
D207  USERCOMPTEXT3: TOSHIBA  VAL3: CMH01  (hidden comment: D)
D208  USERCOMPTEXT3: TOSHIBA  VAL3: CMH01  (hidden comment: D)
DP151  VAL3: ]1.5mm  COMPCOMMENT: Q151(D)  (hidden comment: TP)
DP152  VAL3: ]1.5mm  (hidden comment: TP)
DP153  VAL3: ]1.5mm  (hidden comment: TP)
DP154  VAL3: ]1.5mm  COMPCOMMENT: Q153(D)  (hidden comment: TP)
DP155  VAL3: ]1.5mm  (hidden comment: TP)
DP156  VAL3: ]1.5mm  (hidden comment: TP)
DP157  VAL3: HK-2-S  COMPCOMMENT: T151-L  (hidden comment: TP)
DP201  VAL3: ]1.5mm  (hidden comment: TP)
DP202  VAL3: ]1.5mm  (hidden comment: TP)
DP203  VAL3: HK-2-S  COMPCOMMENT: T201-L  (hidden comment: TP)
DP501  VAL3: LC-22-S-BLACK  (hidden comment: TP)
IC151  L27524  (value not drawn)
IC201  L27524  (value not drawn)
L151  CTW18A27uH
L201  CTW18A27uH
Q151  VAL3: TPM7R10CQ5  USERCOMPTEXT3: TOSHIBA  (hidden comment: NCHMOSFET_SOPADVANCE-E-01)
Q152  NCHMOSFET_SOPADVANCE-E-01  (value not drawn)
Q153  VAL3: TPM7R10CQ5  USERCOMPTEXT3: TOSHIBA  (hidden comment: NCHMOSFET_SOPADVANCE-E-01)
Q154  NCHMOSFET_SOPADVANCE-E-01  (value not drawn)
Q201  VAL3: TPM7R10CQ5  USERCOMPTEXT3: TOSHIBA  (hidden comment: NCHMOSFET_SOPADVANCE-E-01)
Q202  NCHMOSFET_SOPADVANCE-E-01  (value not drawn)
Q203  VAL3: TPM7R10CQ5  USERCOMPTEXT3: TOSHIBA  (hidden comment: NCHMOSFET_SOPADVANCE-E-01)
Q204  NCHMOSFET_SOPADVANCE-E-01  (value not drawn)
R151  VAL1: 1(J)  SIZECODESMD: 1005  (hidden comment: R)
R152  VAL1: 10(J)  SIZECODESMD: 2012  (hidden comment: R)
R153  VAL1: 3(J)  SIZECODESMD: 2012  (hidden comment: R)
R154  VAL1: 10K(J)  SIZECODESMD: 1005  (hidden comment: R)
R155  VAL2: 2W  VAL1: 620(J)  SIZECODESMD: 6432  (hidden comment: R)
R156  VAL1: 10(J)  SIZECODESMD: 2012  (hidden comment: R)
R157  VAL1: 3(J)  SIZECODESMD: 2012  (hidden comment: R)
R158  VAL1: 10K(J)  SIZECODESMD: 1005  (hidden comment: R)
R159  VAL2: 2W  VAL1: 620(J)  SIZECODESMD: 6432  (hidden comment: R)
R160  VAL1: 100K(F)  SIZECODESMD: 3216  (hidden comment: R)
R161  NOTMOUNT: NOT MOUNT  SIZECODESMD: 3216  (hidden comment: R)
R162  VAL2: 2W  VAL1: 27K(J)  SIZECODESMD: 6432  (hidden comment: R)
R163  VAL2: 2W  VAL1: 27K(J)  SIZECODESMD: 6432  (hidden comment: R)
R164  VAL1: 0  SIZECODESMD: 1005  (hidden comment: R)
R165  VAL1: 0  SIZECODESMD: 1005  (hidden comment: R)
R201  VAL1: 1(J)  SIZECODESMD: 1005  (hidden comment: R)
R202  VAL1: 10(J)  SIZECODESMD: 2012  (hidden comment: R)
R203  VAL1: 3(J)  SIZECODESMD: 2012  (hidden comment: R)
R204  VAL1: 10K(J)  SIZECODESMD: 1005  (hidden comment: R)
R205  VAL2: 2W  VAL1: 620(J)  SIZECODESMD: 6432  (hidden comment: R)
R206  VAL1: 10(J)  SIZECODESMD: 2012  (hidden comment: R)
R207  VAL1: 3(J)  SIZECODESMD: 2012  (hidden comment: R)
R208  VAL1: 10K(J)  SIZECODESMD: 1005  (hidden comment: R)
R209  VAL2: 2W  VAL1: 620(J)  SIZECODESMD: 6432  (hidden comment: R)
R210  VAL1: 100K(F)  SIZECODESMD: 3216  (hidden comment: R)
R211  NOTMOUNT: NOT MOUNT  SIZECODESMD: 3216  (hidden comment: R)
R212  VAL2: 2W  VAL1: 27K(J)  SIZECODESMD: 6432  (hidden comment: R)
R213  VAL2: 2W  VAL1: 27K(J)  SIZECODESMD: 6432  (hidden comment: R)
R214  VAL1: 0  SIZECODESMD: 1005  (hidden comment: R)
R215  VAL1: 0  SIZECODESMD: 1005  (hidden comment: R)
R501  VAL1: 10K(J)  SIZECODESMD: 6332  (hidden comment: R)
R502  NOTMOUNT: NOT MOUNT  (hidden comment: R)
R503  NOTMOUNT: NOT MOUNT  (hidden comment: R)
T151  VAL1: 27:4:4  VAL3: 08C26031  (hidden comment: T3_12V67A)
T201  VAL1: 27:4:4  VAL3: 08C26031  (hidden comment: T3_12V67A)
U?#4  DATE: 2026/08/07  DRAWINGNUMBER: RD250-SCHEMATIC-01  TITLE: 1.6kW 48V Output Telecomunication / Equipment Power Supply(Upgraded)  FUNCTION: PSFB - Synchronous Rectification  SHEETNUMBER: 4/8  REVISION: 01  (hidden comment: WAKU_A3_TDSC_PSDEV_LOCAL)

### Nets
LGND: C151.1 C152.1 C153.1 C156.1 C157.1 C158.1 C159.1 C201.1 C202.1 C203.1 C206.1 C207.1 C208.1 C209.1 C501.1 C502.1 C503.1 C504.1 C505.1 C506.1 C507.1 C508.1 D153.C D203.C DP153.1 DP156.1 DP501.1 IC151.3 IC201.3 Q151.1 Q151.2 Q151.3 Q152.1 Q152.2 Q152.3 Q153.1 Q153.2 Q153.3 Q154.1 Q154.2 Q154.3 Q201.1 Q201.2 Q201.3 Q202.1 Q202.2 Q202.3 Q203.1 Q203.2 Q203.3 Q204.1 Q204.2 Q204.3 R154.1 R155.1 R158.1 R159.1 R160.1 R161.1 R204.1 R205.1 R208.1 R209.1 R210.1 R211.1 R501.1 R502.1 R503.1
VCC12R0_2: R151.1 R201.1
CONN002: CN101.1 CN104.1 ; off-sheet CONN002
CONN003: CN103.1 CN106.1 ; off-sheet CONN003
CONN004: C501.2 C502.2 C503.2 C504.2 C505.2 C506.2 C507.2 C508.2 L151.F L201.F R162.2 R163.2 R212.2 R213.2 R501.2 R502.2 R503.2 ; off-sheet CONN004
OUTE: R164.1 R214.1 ; off-sheet OUTE
OUTF: R165.1 R215.1 ; off-sheet OUTF
SIG115: C204.2 CN201.1 D207.A Q201.5 Q201.6 Q201.7 Q201.8 Q202.5 Q202.6 Q202.7 Q202.8
SIG00429: C151.2 C152.2 C153.2 IC151.6 R151.2
SIG00430: D151.C R152.1
SIG00431: D152.A R153.1
SIG00432: D154.C R156.1
SIG00433: D156.A R157.1
SIG00434: D201.C R202.1
SIG00435: D202.A R203.1
SIG00436: D204.C R206.1
SIG00437: D206.A R207.1
SIG00438: D201.A D202.C D203.A IC201.7
SIG00439: DP155.1 Q153.4 Q154.4 R156.2 R157.2 R158.2
SIG00440: DP202.1 Q203.4 Q204.4 R206.2 R207.2 R208.2
SIG00445: C205.2 CN202.1 D208.A Q203.5 Q203.6 Q203.7 Q203.8 Q204.5 Q204.6 Q204.7 Q204.8
SIG00446: CN153.1 DP157.1 L151.S
SIG00447: C154.2 CN151.1 D157.A DP151.1 Q151.5 Q151.6 Q151.7 Q151.8 Q152.5 Q152.6 Q152.7 Q152.8
SIG00448: CN203.1 DP203.1 L201.S
SIG00449: DP152.1 Q151.4 Q152.4 R152.2 R153.2 R154.2
SIG00450: DP201.1 Q201.4 Q202.4 R202.2 R203.2 R204.2
SIG00451: C158.2 IC151.2 R164.2
SIG00452: C159.2 IC151.4 R165.2
SIG00453: C208.2 IC201.2 R214.2
SIG00454: D153.NC D154.A D156.C IC151.5
SIG00455: D203.NC D204.A D206.C IC201.5
SIG00456: D151.A D152.C D153.A IC151.7
SIG00457: C155.2 CN152.1 D158.A DP154.1 Q153.5 Q153.6 Q153.7 Q153.8 Q154.5 Q154.6 Q154.7 Q154.8
SIG00458: C156.2 C157.2 D157.C D158.C R160.2 R161.2 R162.1 R163.1
SIG00459: C201.2 C202.2 C203.2 IC201.6 R201.2
SIG00460: C209.2 IC201.4 R215.2
SIG00461: C206.2 C207.2 D207.C D208.C R210.2 R211.2 R212.1 R213.1
NetC154_1: C154.1 R155.2
NetC155_1: C155.1 R159.2
NetC204_1: C204.1 R205.2
NetC205_1: C205.1 R209.2

Not connected (* = marked no-connect by the designer): CN102 1; CN105 1; IC151 1 8; IC201 1 8; T151 1 3 4 6 7 8 9 10 11 12; T201 1 3 4 6 7 8 9 10 11 12

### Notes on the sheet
- Primary
- Secondary
- Q151,Q152:
- (near DP157) Q153,Q154:
- C501-C505:
- Q201,Q202:
- Q203,Q204:

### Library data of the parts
C151 C152 C201 C202 = C_Dup1: as C55 on sheet 2
C153 C158 C159 C203 C208 C209 = C_Dup1: as C53 on sheet 2
C154 C155 C204 C205 C506-C508 = GRM21BC71E106KE01: TIME: 10:25:11; UPDATEUSER: t4887876; UPDATETIME: 16:23:00; SAVECOUNT: 11; MAKER: Murata; OriginalSymbolOrigin: (2540,7620); CHIPSIZE: 1005; MAXGCOUNT: 1
C156 C157 C206 C207 = C: SQ_PART_MODEL: CON_150N; OriginalSymbolOrigin: (2540,7620); GATENO: 1; ADSCNVFLAG: ON; ADSCOMPONENTNAME: C_4532; COMP: K0301583; CHIPSIZE: 1005; SAVECOUNT: 0
C501 = CP: SAVEAREA0: -1450,-153,20294,13055; SAVECOUNT: 52; TIME: 15:02:55; UPDATEUSER: fukuda-y; UPDATETIME: 16:13:42; VAL1: 330uF(M); VAL2: 63V; OriginalSymbolOrigin: (2540,10160); COMP: PRT_3; CHIPSIZE: D10xL22; MAXGCOUNT: 1; SIZECODESMD: DIP
C502-C505 = CP: SAVEAREA0: -1450,-153,20294,13055; SAVECOUNT: 52; TIME: 15:02:55; UPDATEUSER: fukuda-y; UPDATETIME: 16:13:42; VAL1: 330uF(M); VAL2: 63V; OriginalSymbolOrigin: (2540,10160); COMPCOMMENT: EKZN630ELL331MJ25S; COMP: PRT_3; CHIPSIZE: D10xL22; MAXGCOUNT: 1; SIZECODESMD: DIP
CN101-CN106 = LONGHOLE_2R5-4R5: TIME: 17:17:39; UPDATEUSER: t4887876; UPDATETIME: 09:28:53; SAVECOUNT: 11; VAL3: PCB Pad; OriginalSymbolOrigin: (5080,5080)
CN151 CN152 CN201 CN202 = TH_PHI_3R5: TIME: 17:17:39; UPDATEUSER: t4887876; UPDATETIME: 10:33:19; SAVECOUNT: 10; VAL3: PCB Pad; OriginalSymbolOrigin: (5080,5080)
CN153 CN203 = LONGHOLE_3R5-7R0: TIME: 17:17:39; UPDATEUSER: t4887876; UPDATETIME: 09:28:53; SAVECOUNT: 12; VAL3: PCB Pad; OriginalSymbolOrigin: (5080,5080)
D151 D152 D154 D156 D201 D202 D204 D206 = CUHS15S30: as D102 on sheet 3
D153 D203 = DEK_RD244: SAVEAREA0: -5273,-211,27850,20882; TIME: 14:49:55; UPDATEUSER: t6860224; UPDATETIME: 15:08:32; SAVECOUNT: 13; OriginalSymbolOrigin: (0,20320); USERCOMPTEXT2: 30V,0.2A; COMP: PRT_25
D157 D158 D207 D208 = D_Dup1: SAVEAREA0: -225,-91,12804,7836; SAVECOUNT: 3; TIME: 14:49:55; UPDATEUSER: 19870035; UPDATETIME: 14:20:16; OriginalSymbolOrigin: (5080,5080); USERCOMPTEXT2: 200V,3A; COMP: PRT_14; MAXGCOUNT: 1
DP151-DP156 DP201 DP202 = TP: as DP52 on sheet 2
DP157 DP203 = TP: as DP1 on sheet 2
DP501 = TP: TIME: 16:12:21; UPDATEUSER: fukuda-y; UPDATETIME: 16:18:11; SAVECOUNT: 2; SAVEAREA0: -242,-92,12810,7836; OriginalSymbolOrigin: (0,7620); COMP: PRT_34
IC151 IC201 = L27524: as IC51 on sheet 2
L151 L201 = CTW18A27UH: SAVECOUNT: 9; SAVEAREA0: -384,-828,17939,11225; TIME: 16:55:46; UPDATEUSER: t4887876; UPDATETIME: 20:23:23; VAL1: 31uH; VAL2: 18A; MAKER: TAMURA; OriginalSymbolOrigin: (2540,5080); MAXGCOUNT: 1
Q151 Q153 Q201 Q203 = NCHMOSFET_SOPADVANCE-E-01: TIME: 18:29:30; UPDATEUSER: t4887876; UPDATETIME: 14:15:50; SAVECOUNT: 31; SAVEAREA0: -10143,-336,37609,28718; COMP: NchMOSFET_SOPAdvance_E-01; VAL2: R・&¦#ﾐ{¦; CHIPSET: R獸¦#ﾐ{¦; OriginalSymbolOrigin: (5080,22860); MAXGCOUNT: 1
Q152 Q154 Q202 Q204 = NCHMOSFET_SOPADVANCE-E-01: TIME: 18:29:30; UPDATEUSER: t4887876; UPDATETIME: 14:15:50; SAVECOUNT: 31; SAVEAREA0: -10143,-336,37609,28718; COMP: NchMOSFET_SOPAdvance_E-01; VAL3: TPM7R10CQ5; VAL2: R・&¦#ﾐ{¦; CHIPSET: R獸¦#ﾐ{¦; OriginalSymbolOrigin: (5080,22860); MAXGCOUNT: 1; USERCOMPTEXT3: TOSHIBA
R151 R154 R158 R201 R204 R208 = R_Dup1: as R4 on sheet 1
R152 R153 R156 R157 R202 R203 R206 R207 = R_Dup1: as R54 on sheet 2
R155 R159 R205 R209 = R_Dup1: OriginalSymbolOrigin: (5080,5080); COMP: PRT_43; VAL3: CRGH2512J620R; MAXGCOUNT: 1; SAVECOUNT: 0
R160 R210 = R_Dup1: VAL2: 250mW; OriginalSymbolOrigin: (5080,5080); COMP: PRT_5; MAXGCOUNT: 1; ADSCOMPONENTNAME: R_3216; SAVECOUNT: 0
R161 R211 = R_Dup1: OriginalSymbolOrigin: (5080,5080); COMP: PRT_5; MAXGCOUNT: 1; ADSCOMPONENTNAME: R_3216; SAVECOUNT: 0
R162 R163 R212 R213 = R: SQ_PART_MODEL: RES_47K; OriginalSymbolOrigin: (5080,5080); VAL3: CRGH2512J27K; ADSCNVFLAG: ON; COMP: CRGH2512J620R; MAXGCOUNT: 1; SAVECOUNT: 0
R164 R165 R214 R215 = R_Dup1: as R97 on sheet 2
R501 = R: SQ_PART_MODEL: RES_47K; VAL2: 1W; OriginalSymbolOrigin: (5080,5080); ADSCNVFLAG: ON; ADSCOMPONENTNAME: R_6332; COMP: GDM010001640; CHIPSIZE: 6432; MAXGCOUNT: 1; SAVECOUNT: 0
R502 R503 = R: SQ_PART_MODEL: RES_47K; OriginalSymbolOrigin: (5080,5080); ADSCNVFLAG: ON; ADSCOMPONENTNAME: R_6332; SIZECODESMD: 6332; COMP: GDM010001640; CHIPSIZE: 6432; MAXGCOUNT: 1; SAVECOUNT: 0
T151 T201 = TAM0545: UPDATEUSER: t4887876; UPDATETIME: 19:36:27; SAVECOUNT: 21; TIME: 16:40:06; SAVEAREA0: -9901,-21944,29587,7006; ORIGINALSYMBOLORIGIN: (-7620,0)
U?#4 = WAKU_A3_TDSC_PSDEV_LOCAL: PLOTTIME: HH:MM; SAVEAREA0: -311037,-554865,914355,115662; TIME: 12:01:09; UPDATEUSER: t5459927; UPDATETIME: 17:59:49; SAVECOUNT: 3; ZONEOFFSETX: 36; ZONEOFFSETY: -24; OriginalSymbolOrigin: (0,434340); SHTSAVECOUNT: 172; PAGENUMBER: 4; DESIGNED: TOSHIBA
